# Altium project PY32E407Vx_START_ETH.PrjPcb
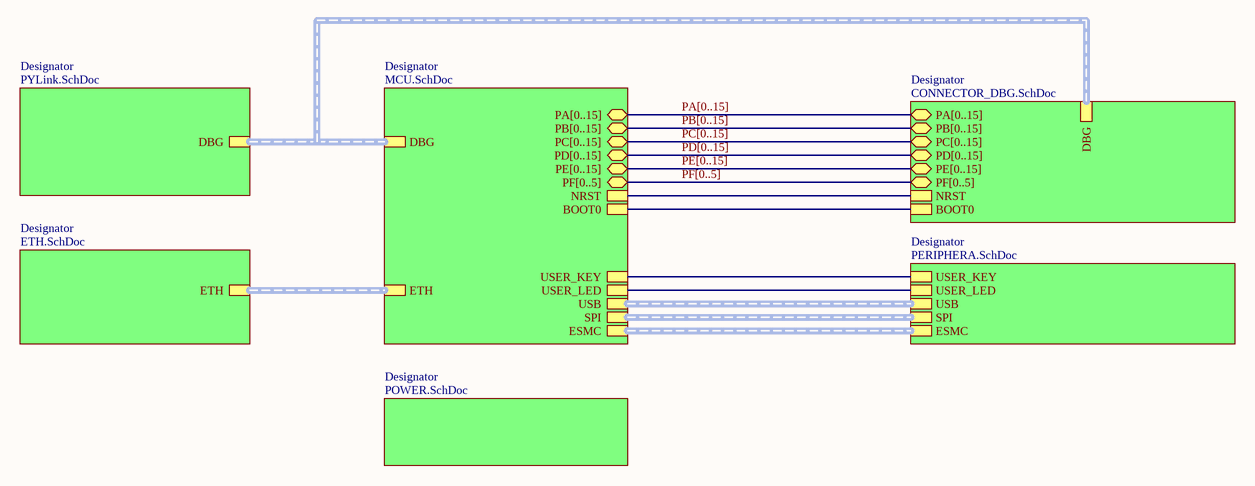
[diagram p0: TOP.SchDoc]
7 sheets, 253 parts. Net scope: hierarchical (ports join the sheet entries above them; power ports are global).
Board file: PY32E407Vx_START_ETH.PcbDoc
Sheets:
  TOP.SchDoc
    Designator = PYLink.SchDoc
    Designator = MCU.SchDoc
    Designator = ETH.SchDoc
    Designator = PERIPHERA.SchDoc
    Designator = CONNECTOR_DBG.SchDoc
    Designator = POWER.SchDoc

## Sheet TOP.SchDoc: TOP
size A4; Revision: V2.0; SheetNumber: 1; SheetTotal: 7; Project: PY32F403v1xT_START

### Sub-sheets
Designator = PYLink.SchDoc: DBG (harness QSPI)
Designator = MCU.SchDoc: PA[0..15] (bidir), PB[0..15] (bidir), PC[0..15] (bidir), PD[0..15] (bidir), PE[0..15] (bidir), NRST, BOOT0, ETH (harness QSPI), USB (harness QSPI), ESMC (harness QSPI), SPI (harness QSPI), DBG (harness QSPI), PF[0..5] (bidir), USER_KEY, USER_LED
Designator = ETH.SchDoc: ETH (harness QSPI)
Designator = PERIPHERA.SchDoc: USB (harness QSPI), ESMC (harness QSPI), SPI (harness QSPI), USER_KEY, USER_LED
Designator = CONNECTOR_DBG.SchDoc: PA[0..15] (bidir), PB[0..15] (bidir), PC[0..15] (bidir), PD[0..15] (bidir), PE[0..15] (bidir), NRST, BOOT0, DBG (harness QSPI), PF[0..5] (bidir)
Designator = POWER.SchDoc: no entries

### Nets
BOOT0: sheet Designator/BOOT0, sheet Designator/BOOT0
NRST: sheet Designator/NRST, sheet Designator/NRST
USER_KEY: sheet Designator/USER_KEY, sheet Designator/USER_KEY
USER_LED: sheet Designator/USER_LED, sheet Designator/USER_LED

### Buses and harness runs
bus PA[0..15] = sheet Designator/PA[0..15]
bus PB[0..15] = sheet Designator/PB[0..15]
bus PC[0..15] = sheet Designator/PC[0..15]
bus PD[0..15] = sheet Designator/PD[0..15]
bus PE[0..15] = sheet Designator/PE[0..15]
bus PF[0..5] = sheet Designator/PF[0..5]

## Sheet PYLink.SchDoc: PYLink
size A3; DrawnBy: lcg; Revision: V2.0; SheetNumber: 2; SheetTotal: 7; Project: PY32F403v1xT_START
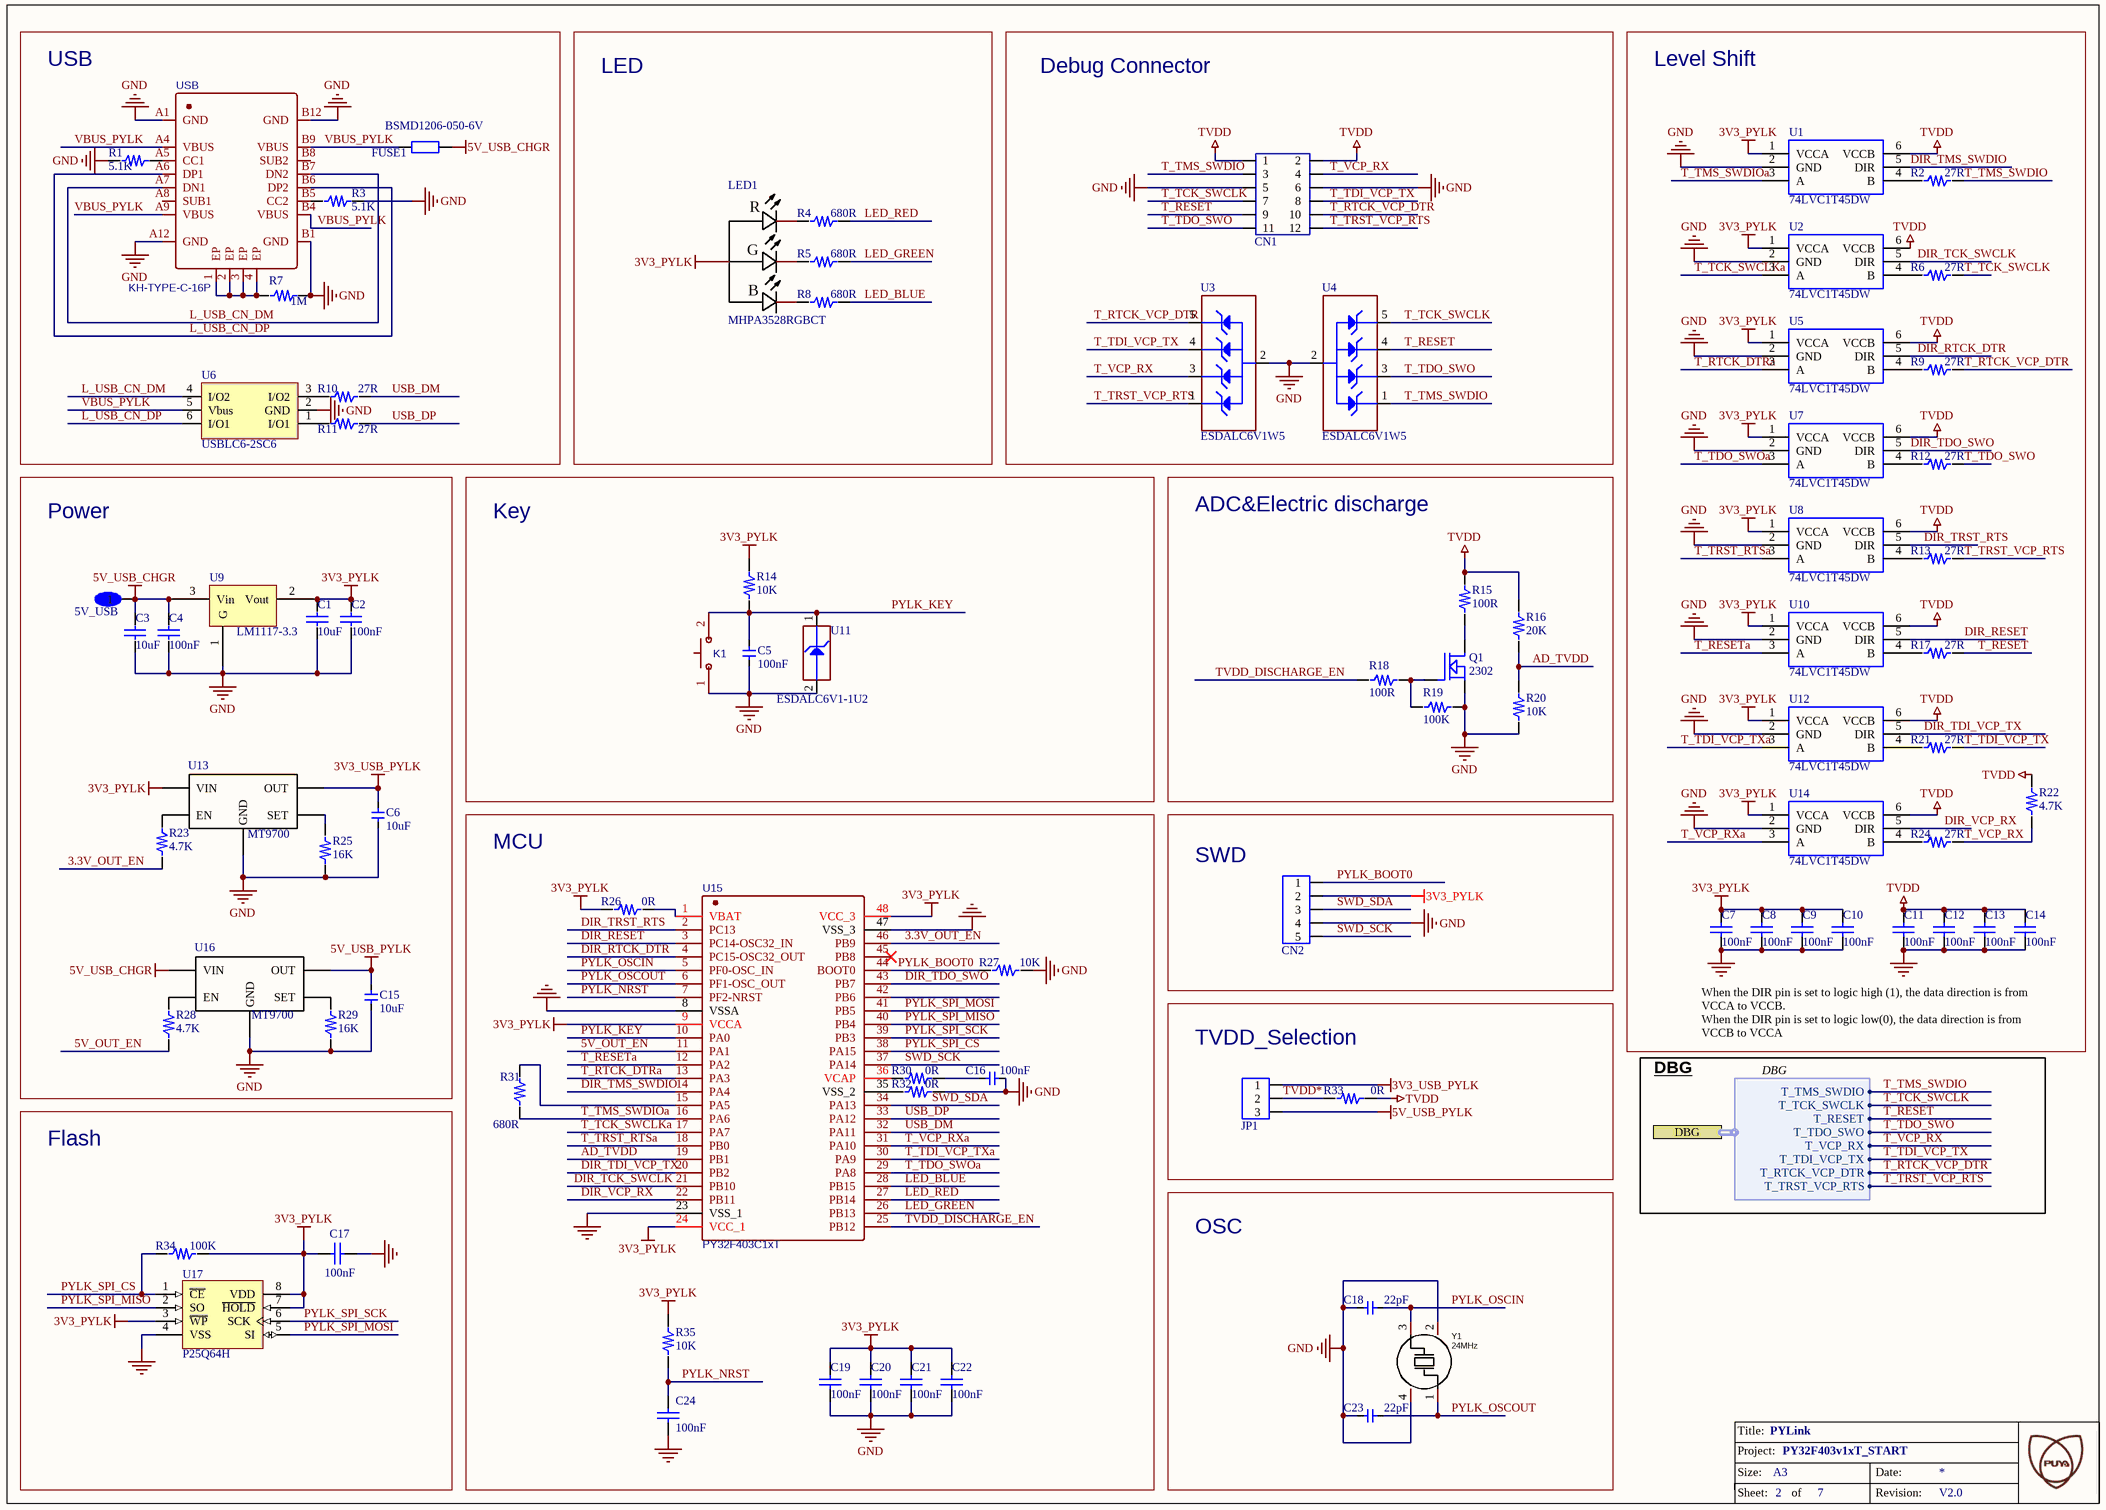
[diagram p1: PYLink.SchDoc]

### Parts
5V_USB  TP_SIN  [TP_SIN]  (value not drawn)
C1  10uF  [C0805]
C2  100nF  [C0603]
C3  10uF  [C0805]
C4  100nF  [C0603]
C5  100nF  [C0603]
C6  10uF  [C0805]
C7  100nF  [C0603]
C8  100nF  [C0603]
C9  100nF  [C0603]
C10  100nF  [C0603]
C11  100nF  [C0603]
C12  100nF  [C0603]
C13  100nF  [C0603]
C14  100nF  [C0603]
C15  10uF  [C0805]
C16  100nF  [C0603]
C17  100nF  [C0603]
C18  22pF  [C0603]
C19  100nF  [C0603]
C20  100nF  [C0603]
C21  100nF  [C0603]
C22  100nF  [C0603]
C23  22pF  [C0603]
C24  100nF  [C0603]
CN1  CON6x2  [CON6x2]  (value not drawn)
CN2  CON5  [CON5]  (value not drawn)
FUSE1  BSMD1206-050-6V  [SDM1210P005TF]
JP1  CON3  [CON3]  (value not drawn)
K1  1TS002B-2600-5001_key  [Switch]  (value not drawn)
LED1  MHPA3528RGBCT  [LED-ARRAY-SMD_4P-L3.5-W2.8-TL]
Q1  2302  [SOT23]
R1  5.1K  [R0603]
R2  27R  [R0603]
R3  5.1K  [R0603]
R4  680R  [R0603]
R5  680R  [R0603]
R6  27R  [R0603]
R7  1M  [R0603]
R8  680R  [R0603]
R9  27R  [R0603]
R10  27R  [R0603]
R11  27R  [R0603]
R12  27R  [R0603]
R13  27R  [R0603]
R14  10K  [R0603]
R15  100R  [R0805]
R16  20K  [R0603]
R17  27R  [R0603]
R18  100R  [R0603]
R19  100K  [R0603]
R20  10K  [R0603]
R21  27R  [R0603]
R22  4.7K  [R0603]
R23  4.7K  [R0603]
R24  27R  [R0603]
R25  16K  [R0603]
R26  0R  [R0603]
R27  10K  [R0603]
R28  4.7K  [R0603]
R29  16K  [R0603]
R30  0R  [R0603]
R31  680R  [R0603]
R32  0R  [R0603]
R33  0R  [R0603]
R34  100K  [R0603]
R35  10K  [R0603]
U1  74LVC1T45DW  [SOT363]
U2  74LVC1T45DW  [SOT363]
U3  value ESDALC6V1W5  [ESD_SOT323-5L]  (hidden comment: ESD_6V1)
U4  value ESDALC6V1W5  [ESD_SOT323-5L]  (hidden comment: ESD_6V1)
U5  74LVC1T45DW  [SOT363]
U6  USBLC6-2SC6  [SOT23-6]
U7  74LVC1T45DW  [SOT363]
U8  74LVC1T45DW  [SOT363]
U9  LM1117-3.3  [LM1117-3.3]
U10  74LVC1T45DW  [SOT363]
U11  value ESDALC6V1-1U2  [ESD_ST0201]  (hidden comment: ESD-TRANSIL)
U12  74LVC1T45DW  [SOT363]
U13  MT9700  [SOT23-5]
U14  74LVC1T45DW  [SOT363]
U15  PY32F403C1xT  [LQFP-48_L7.0-W7.0-P0.50-LS9.0-BL]
U16  MT9700  [SOT23-5]
U17  P25Q64H  [SOP-8P]
USB  KH-TYPE-C-16P  [USB-C-SMD_KH-TYPE-C-16P]
Y1  24MHz  [CRYSTAL-SMD_4P-L3.2-W2.5-BL]

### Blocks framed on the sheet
USB: FUSE1 R1 R3 R7 R10 R11 U6 USB
LED: LED1 R4 R5 R8
Debug Connector: CN1 U3 U4
Level Shift: C7-C14 R2 R6 R9 R12 R13 R17 R21 R22 R24 U1 U2 U5 U7 U8 U10 U12 U14
Power: 5V_USB C1-C4 C6 C15 R23 R25 R28 R29 U9 U13 U16
Key: C5 K1 R14 U11
ADC&Electric discharge: Q1 R15 R16 R18-R20
MCU: C16 C19-C22 C24 R26 R27 R30-R32 R35 U15
SWD: CN2
TVDD_Selection: JP1 R33
Flash: C17 R34 U17
OSC: C18 C23 Y1

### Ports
DBG (harness DBG)

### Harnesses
DBG: T_VCP_RX, T_TDO_SWO, T_RESET, T_TMS_SWDIO, T_TDI_VCP_TX, T_TCK_SWCLK, T_RTCK_VCP_DTR, T_TRST_VCP_RTS

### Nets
3V3_PYLK: C1.2 C2.2 C7.2 C8.2 C9.2 C10.2 C17.2 C19.2 C20.2 C21.2 C22.2 CN2.2 LED1.1(-) R14.2 R26.1 R34.2 R35.2 U1.1(VCCA) U2.1(VCCA) U5.1(VCCA) U7.1(VCCA) U8.1(VCCA) U9.2(Vout) U10.1(VCCA) U12.1(VCCA) U13.5(VIN) U14.1(VCCA) U15.9(VCCA) U15.24(VCC_1) U15.48(VCC_3) U17.3(~{WP}) U17.7(~{HOLD}) U17.8(VDD)
3V3_USB_PYLK: C6.2 JP1.1 U13.1(OUT)
5V_USB_CHGR: 5V_USB.1 C3.2 C4.2 FUSE1.2 U9.3(Vin) U16.5(VIN)
5V_USB_PYLK: C15.2 JP1.3 U16.1(OUT)
GND: C1.1 C2.1 C3.1 C4.1 C5.1 C6.1 C7.1 C8.1 C9.1 C10.1 C11.1 C12.1 C13.1 C14.1 C15.1 C16.1 C17.1 C18.1 C19.1 C20.1 C21.1 C22.1 C23.1 C24.1 CN1.5 CN1.6 CN2.4 K1.1(A) Q1.2(S) R1.1 R3.2 R7.2 R19.1 R20.1 R25.1 R27.2 R29.1 R32.2 U1.2(GND) U2.2(GND) U3.2(GND) U4.2(GND) U5.2(GND) U6.2(GND) U7.2(GND) U8.2(GND) U9.1(G) U10.2(GND) U11.2(GND) U12.2(GND) U13.2(GND) U14.2(GND) U15.8(VSSA) U15.23(VSS_1) U15.47(VSS_3) U16.2(GND) U17.4(VSS) USB.A1(GND) USB.A12(GND) USB.B1(GND) USB.B12(GND) Y1.2(GND) Y1.4(GND)
TVDD: C11.2 C12.2 C13.2 C14.2 CN1.1 CN1.2 R15.2 R16.2 R22.2 R33.2 U1.6(VCCB) U2.6(VCCB) U5.6(VCCB) U7.6(VCCB) U8.6(VCCB) U10.6(VCCB) U12.6(VCCB) U14.6(VCCB)
3.3V_OUT_EN: R23.1 U15.46(PB9)
5V_OUT_EN: R28.1 U15.11(PA1)
AD_TVDD: R16.1 R20.2 U15.19(PB1)
DIR_RESET: U10.5(DIR) U15.3(PC14-OSC32_IN)
DIR_RTCK_DTR: U5.5(DIR) U15.4(PC15-OSC32_OUT)
DIR_TCK_SWCLK: U2.5(DIR) U15.21(PB10)
DIR_TDI_VCP_TX: U12.5(DIR) U15.20(PB2)
DIR_TDO_SWO: U7.5(DIR) U15.43(PB7)
DIR_TMS_SWDIO: U1.5(DIR) U15.14(PA4)
DIR_TRST_RTS: U8.5(DIR) U15.2(PC13)
DIR_VCP_RX: U14.5(DIR) U15.22(PB11)
L_USB_CN_DM: U6.4(I/O2) USB.A7(DN1) USB.B7(DN2)
L_USB_CN_DP: U6.6(I/O1) USB.A6(DP1) USB.B6(DP2)
LED_BLUE: R8.2 U15.28(PB15)
LED_GREEN: R5.2 U15.26(PB13)
LED_RED: R4.2 U15.27(PB14)
PYLK_BOOT0: CN2.1 R27.1 U15.44(BOOT0)
PYLK_KEY: C5.2 K1.2(B) R14.1 U11.1(IO1) U15.10(PA0)
PYLK_NRST: C24.2 R35.1 U15.7(PF2-NRST)
PYLK_OSCIN: C18.2 U15.5(PF0-OSC_IN) Y1.3(OSC2)
PYLK_OSCOUT: C23.2 U15.6(PF1-OSC_OUT) Y1.1(OSC1)
PYLK_SPI_CS: R34.1 U15.38(PA15) U17.1(~{CE})
PYLK_SPI_MISO: U15.40(PB4) U17.2(SO)
PYLK_SPI_MOSI: U15.41(PB5) U17.5(SI)
PYLK_SPI_SCK: U15.39(PB3) U17.6(SCK)
SWD_SCK: CN2.5 U15.37(PA14)
SWD_SDA: CN2.3 U15.34(PA13)
T_RESET: CN1.9 R17.2 U4.4(IO3) ; port DBG.T_RESET
T_RESETa: U10.3(A) U15.12(PA2)
T_RTCK_DTRa: U5.3(A) U15.13(PA3)
T_RTCK_VCP_DTR: CN1.10 R9.2 U3.5(IO4) ; port DBG.T_RTCK_VCP_DTR
T_TCK_SWCLK: CN1.7 R6.2 U4.5(IO4) ; port DBG.T_TCK_SWCLK
T_TCK_SWCLKa: U2.3(A) U15.17(PA7)
T_TDI_VCP_TX: CN1.8 R21.2 U3.4(IO3) ; port DBG.T_TDI_VCP_TX
T_TDI_VCP_TXa: U12.3(A) U15.30(PA9)
T_TDO_SWO: CN1.11 R12.2 U4.3(IO2) ; port DBG.T_TDO_SWO
T_TDO_SWOa: U7.3(A) U15.29(PA8)
T_TMS_SWDIO: CN1.3 R2.2 U4.1(IO1) ; port DBG.T_TMS_SWDIO
T_TMS_SWDIOa: R31.1 U1.3(A) U15.16(PA6)
T_TRST_RTSa: U8.3(A) U15.18(PB0)
T_TRST_VCP_RTS: CN1.12 R13.2 U3.1(IO1) ; port DBG.T_TRST_VCP_RTS
T_VCP_RX: CN1.4 R22.1 R24.2 U3.3(IO2) ; port DBG.T_VCP_RX
T_VCP_RXa: U14.3(A) U15.31(PA10)
TVDD*: JP1.2 R33.1
TVDD_DISCHARGE_EN: R18.2 U15.25(PB12)
USB_DM: R10.2 U15.32(PA11)
USB_DP: R11.2 U15.33(PA12)
VBUS_PYLK: FUSE1.1 U6.5(Vbus) USB.A4(VBUS) USB.A9(VBUS) USB.B4(VBUS) USB.B9(VBUS)
NetC16_2: C16.2 R30.2
NetLED1_2: LED1.2(-) R8.1
NetLED1_3: LED1.3(-) R5.1
NetLED1_4: LED1.4(-) R4.1
NetQ1_1: Q1.1(G) R18.1 R19.2
NetQ1_3: Q1.3(D) R15.1
NetR1_2: R1.2 USB.A5(CC1)
NetR2_1: R2.1 U1.4(B)
NetR3_1: R3.1 USB.B5(CC2)
NetR6_1: R6.1 U2.4(B)
NetR7_1: R7.1 USB.1(EP) USB.2(EP) USB.3(EP) USB.4(EP)
NetR9_1: R9.1 U5.4(B)
NetR10_1: R10.1 U6.3(I/O2)
NetR11_1: R11.1 U6.1(I/O1)
NetR12_1: R12.1 U7.4(B)
NetR13_1: R13.1 U8.4(B)
NetR17_1: R17.1 U10.4(B)
NetR21_1: R21.1 U12.4(B)
NetR23_2: R23.2 U13.4(EN)
NetR24_1: R24.1 U14.4(B)
NetR25_2: R25.2 U13.3(SET)
NetR26_2: R26.2 U15.1(VBAT)
NetR28_2: R28.2 U16.4(EN)
NetR29_2: R29.2 U16.3(SET)
NetR30_1: R30.1 U15.36(VCAP)
NetR31_2: R31.2 U15.15(PA5)
NetR32_1: R32.1 U15.35(VSS_2)

Not connected (* = marked no-connect by the designer): U15 42(PB6) 45(PB8)*; USB A8(SUB1) B8(SUB2)

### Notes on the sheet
- When the DIR pin is set to logic high (1), the data direction is from VCCA to VCCB.
  When the DIR pin is set to logic low(0), the data direction is from VCCB to VCCA
- DBG

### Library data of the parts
C1 C3 C6 C15 = C0805: PCB DECAL: 0805
C2 C4 C5 C16 C18 C23 = C0603: PCB DECAL: 0603
C7-C14 C17 C19-C22 C24 = 贴片高压陶瓷电容: Capacitor (Semiconductor SIM Model); 器件封装(外观): 0603; Value: 104
CN1 = CON6x2: PCB DECAL: CON5x2
FUSE1 = SMD1210P005TF: https://item.szlcsc.com/947797.html?fromZone=s_s__%25226V%2520500mA%2522
K1 = 1TS002B-2600-5001_key: BOM_Manufacturer: HYP; Contributor: LCSC
LED1 = MHPA3528RGBCT: Manufacturer: MEIHUA(美华); Add into BOM: yes
Q1 = MOSFET N: Value: SI2302
R1-R14 R16-R35 = R0603: PCB DECAL: 0603
R15 = R0805: PCB DECAL: 0805
U3 U4 = ESDALC6V1W5: Dual Transil array for ESD protection; Internal_Part_Number: MCD-00136; Part_Type: Diode; Manufacturer: STMICROELECTRONICS; ECCN_US: EAR99; ECCN_EU: NEC; Provided_By: Subcon; Initial_Board_Reference: MB1262
U6 = USBLC6-2SC6: Function: ESD EMI fliter
U11 = ESD-TRANSIL: ESD protection 6V1; Internal_Part_Number: MCD-00170; Part_Type: Diode; Manufacturer: STMICROELECTRONICS; ECCN_US: EAR99; ECCN_EU: NEC; Provided_By: Subcon; Initial_Board_Reference: MB1274
U15 = PY32F403C1xT: LQFP48; BOM_Manufacturer: PUYA(普冉)
U17 = SST25VF010: Value: SST25VF020B; 器件封装(外观): SOP8
USB = KH-TYPE-C-16P: BOM_Manufacturer: Shenzhen Kinghelm Elec; Contributor: LCSC
Y1 = ABM8AIG-24.000MHZ-82Z-T: ±20ppm , 12.5pF , T_use: -40°C~125°C; Manufacturer: ABRACON; Add into BOM: yes; External load capacitor: 8pF; Frequency Stability(Full temperature range): ±50ppm; Equivalent Series Resistance (ESR): 50Ω

## Sheet MCU.SchDoc: MCU
size A3; Revision: V2.0; SheetNumber: 3; SheetTotal: 7; Project: PY32F403v1xT_START
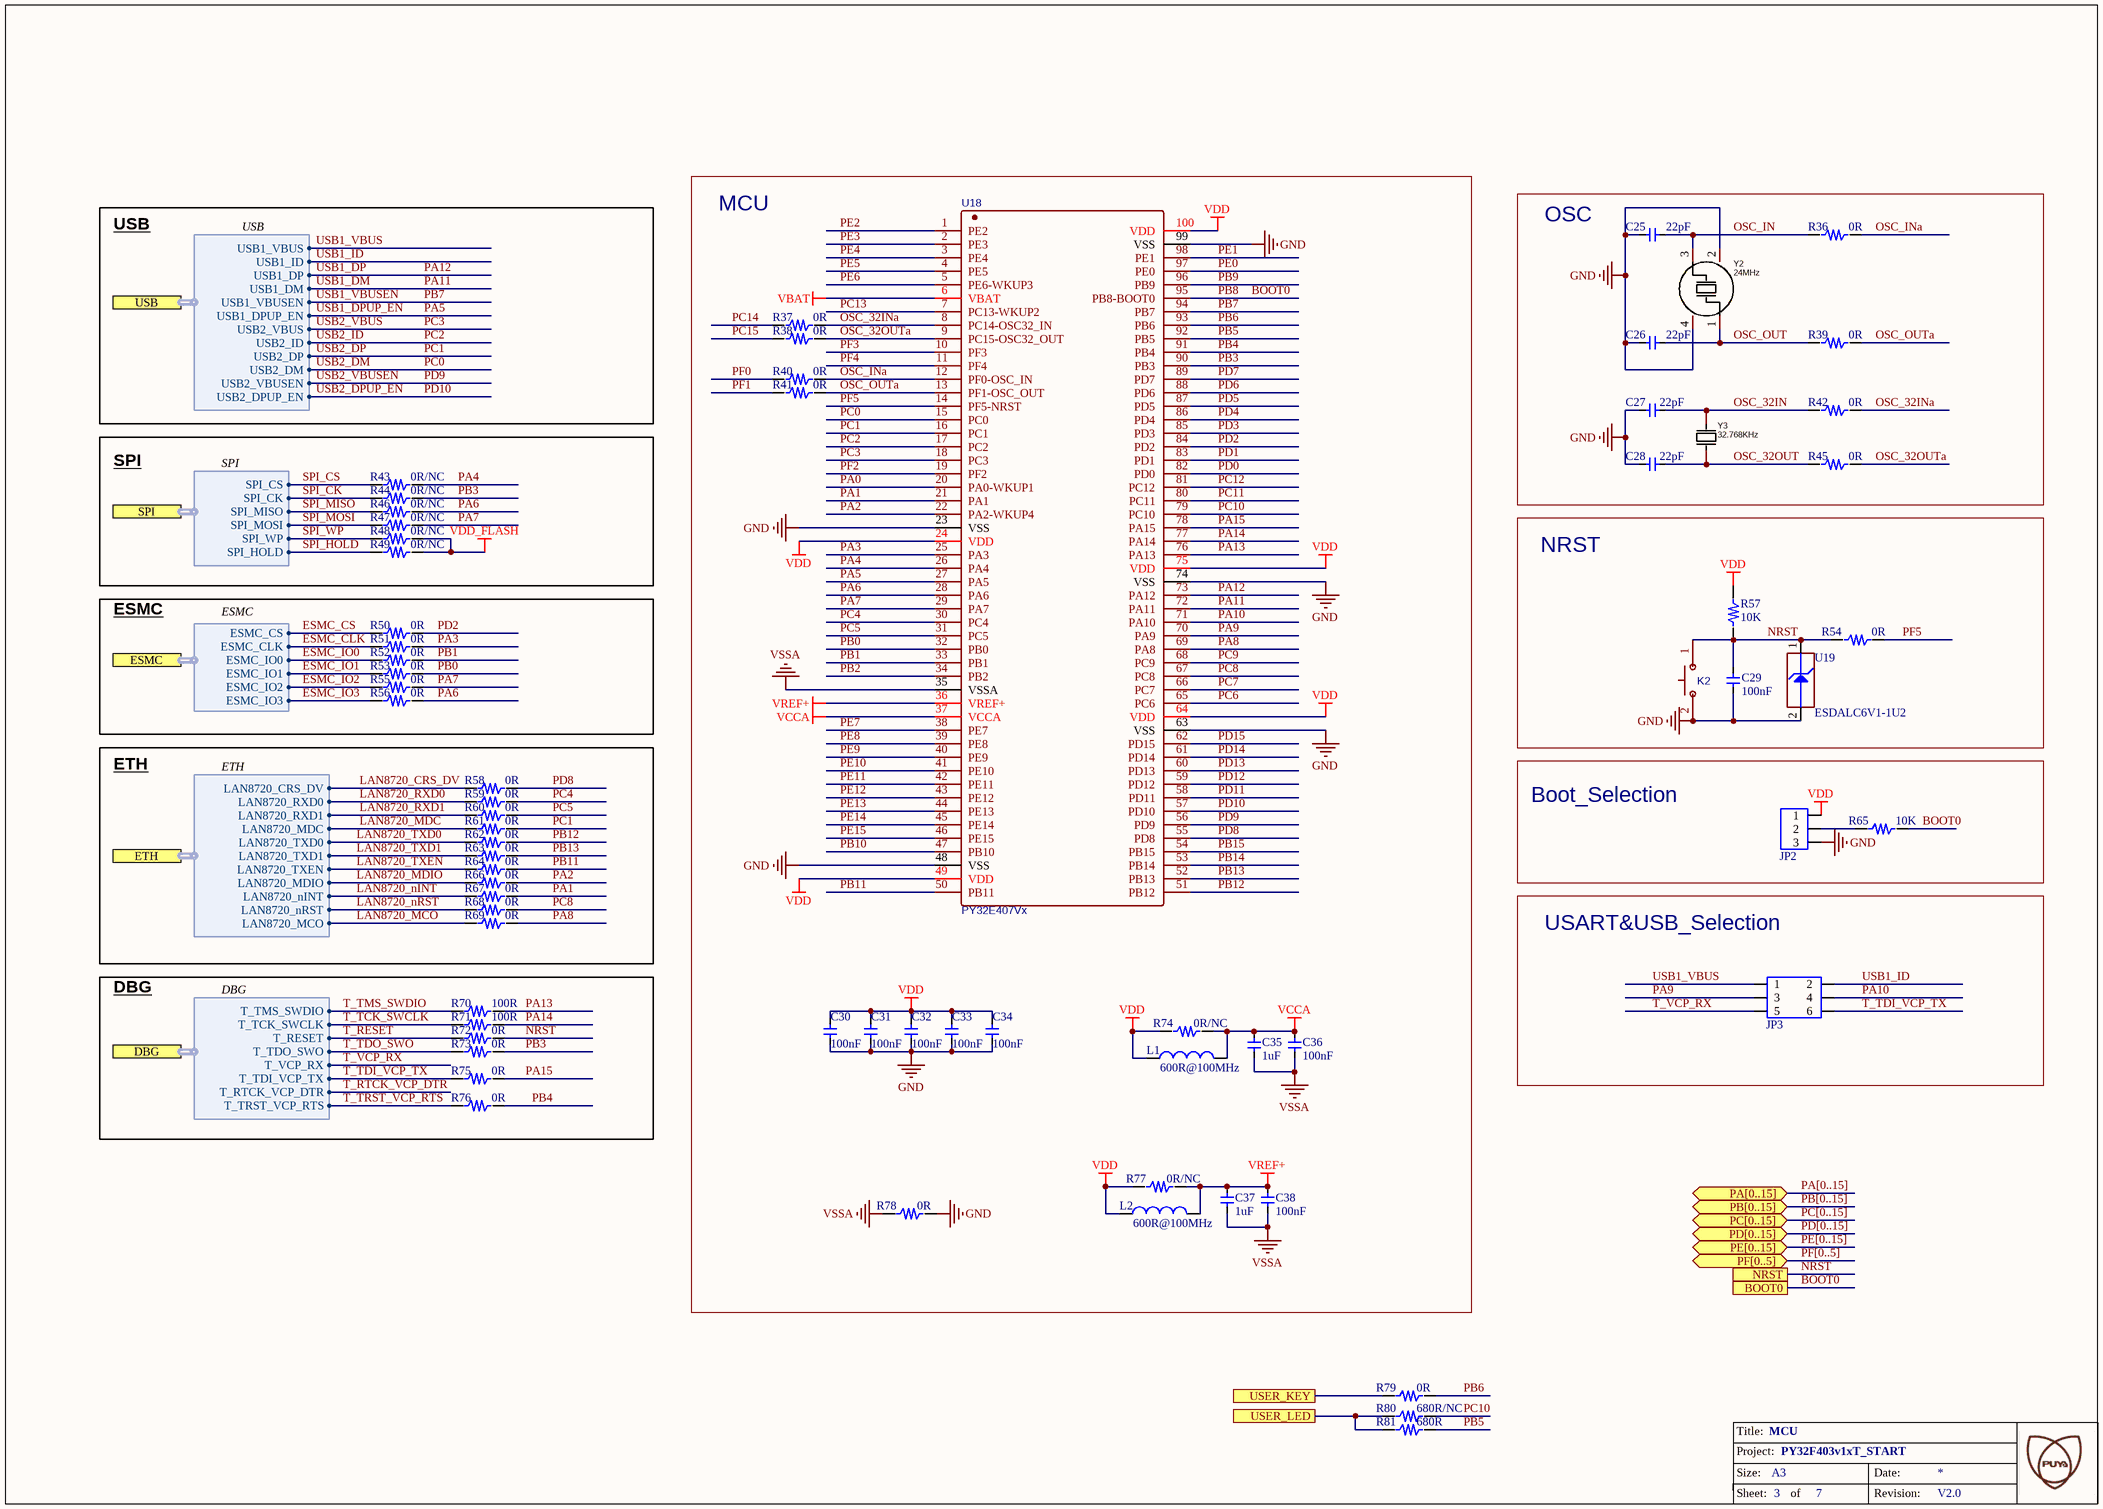
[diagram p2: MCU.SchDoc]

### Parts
C25  22pF  [C0603]
C26  22pF  [C0603]
C27  22pF  [C0603]
C28  22pF  [C0603]
C29  100nF  [C0603]
C30  100nF  [C0603]
C31  100nF  [C0603]
C32  100nF  [C0603]
C33  100nF  [C0603]
C34  100nF  [C0603]
C35  1uF  [C0805]
C36  100nF  [C0603]
C37  1uF  [C0805]
C38  100nF  [C0603]
JP2  CON3  [CON3]  (value not drawn)
JP3  CON3x2  [CON3x2]  (value not drawn)
K2  1TS002B-2600-5001_key  [Switch]  (value not drawn)
L1  value 600R@100MHz  [L0603]  (hidden comment: BEAD)
L2  value 600R@100MHz  [L0603]  (hidden comment: BEAD)
R36  0R  [R0603]
R37  0R  [R0603]
R38  0R  [R0603]
R39  0R  [R0603]
R40  0R  [R0603]
R41  0R  [R0603]
R42  0R  [R0603]
R43  0R/NC  [R0603]
R44  0R/NC  [R0603]
R45  0R  [R0603]
R46  0R/NC  [R0603]
R47  0R/NC  [R0603]
R48  0R/NC  [R0603]
R49  0R/NC  [R0603]
R50  0R  [R0603]
R51  0R  [R0603]
R52  0R  [R0603]
R53  0R  [R0603]
R54  0R  [R0603]
R55  0R  [R0603]
R56  0R  [R0603]
R57  10K  [R0603]
R58  0R  [R0603]
R59  0R  [R0603]
R60  0R  [R0603]
R61  0R  [R0603]
R62  0R  [R0603]
R63  0R  [R0603]
R64  0R  [R0603]
R65  10K  [R0603]
R66  0R  [R0603]
R67  0R  [R0603]
R68  0R  [R0603]
R69  0R  [R0603]
R70  100R  [R0603]
R71  100R  [R0603]
R72  0R  [R0603]
R73  0R  [R0603]
R74  0R/NC  [R0603]
R75  0R  [R0603]
R76  0R  [R0603]
R77  0R/NC  [R0603]
R78  0R  [R0603]
R79  0R  [R0603]
R80  680R/NC  [R0603]
R81  680R  [R0603]
U18  PY32E407Vx  [LQFP-100_L14.0-W14.0-P0.50-LS16.0-BL]
U19  value ESDALC6V1-1U2  [ESD_ST0201]  (hidden comment: ESD-TRANSIL)
Y2  24MHz  [CRYSTAL-SMD_4P-L3.2-W2.5-BL]
Y3  32.768KHz  [CRYSTAL-SMD_L3.2-W1.5-1]

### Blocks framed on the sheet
MCU: C30-C38 L1 L2 R37 R38 R40 R41 R74 R77 R78 U18
OSC: C25-C28 R36 R39 R42 R45 Y2 Y3
SPI: R43 R44 R46-R49
NRST: C29 K2 R54 R57 U19
ESMC: R50-R53 R55 R56
ETH: R58-R64 R66-R69
Boot_Selection: JP2 R65
USART&USB_Selection: JP3
DBG: R70-R73 R75 R76

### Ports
BOOT0, DBG (harness DBG), ESMC (harness ESMC), ETH (harness ETH), NRST, PA[0..15] (bidir), PB[0..15] (bidir), PC[0..15] (bidir), PD[0..15] (bidir), PE[0..15] (bidir), PF[0..5] (bidir), SPI (harness SPI), USB (harness USB), USER_KEY, USER_LED

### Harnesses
ETH: LAN8720_TXD0, LAN8720_MDC, LAN8720_RXD1, LAN8720_CRS_DV, LAN8720_TXD1, LAN8720_TXEN, LAN8720_nINT, LAN8720_MDIO, LAN8720_nRST, LAN8720_RXD0, LAN8720_MCO
ESMC: ESMC_IO2, ESMC_IO1, ESMC_IO0, ESMC_CS, ESMC_IO3, ESMC_CLK
DBG: T_VCP_RX, T_TDO_SWO, T_RESET, T_TMS_SWDIO, T_TDI_VCP_TX, T_TCK_SWCLK, T_RTCK_VCP_DTR, T_TRST_VCP_RTS
USB: USB2_VBUS, USB1_DM, USB1_DP, USB1_VBUS, USB2_ID, USB2_DP, USB2_DM, USB1_ID, USB2_VBUSEN, USB1_VBUSEN, USB1_DPUP_EN, USB2_DPUP_EN
SPI: SPI_MOSI, SPI_MISO, SPI_CS, SPI_CK, SPI_WP, SPI_HOLD

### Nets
GND: C25.1 C26.1 C27.1 C28.1 C29.1 C30.1 C31.1 C32.1 C33.1 C34.1 JP2.3 K2.2(B) R78.2 U18.23(VSS) U18.48(VSS) U18.63(VSS) U18.74(VSS) U18.99(VSS) U19.2(GND) Y2.2(GND) Y2.4(GND)
VBAT: U18.6(VBAT)
VCCA: C35.2 C36.2 L1.2 R74.2 U18.37(VCCA)
VDD: C30.2 C31.2 C32.2 C33.2 C34.2 JP2.1 L1.1 L2.1 R57.1 R74.1 R77.1 U18.24(VDD) U18.49(VDD) U18.64(VDD) U18.75(VDD) U18.100(VDD)
VDD_FLASH: R48.2 R49.2
VREF+: C37.2 C38.2 L2.2 R77.2 U18.36(VREF+)
VSSA: C35.1 C36.1 C37.1 C38.1 R78.1 U18.35(VSSA)
BOOT0: R65.2 U18.95(PB8-BOOT0) ; port BOOT0  [also labelled PB8]
ESMC_CLK: R44.1 R51.1 ; port ESMC.ESMC_CLK, port SPI.SPI_CK  [also labelled SPI_CK]
ESMC_CS: R43.1 R50.1 ; port ESMC.ESMC_CS, port SPI.SPI_CS  [also labelled SPI_CS]
ESMC_IO0: R47.1 R52.1 ; port ESMC.ESMC_IO0, port SPI.SPI_MOSI  [also labelled SPI_MOSI]
ESMC_IO1: R46.1 R53.1 ; port ESMC.ESMC_IO1, port SPI.SPI_MISO  [also labelled SPI_MISO]
ESMC_IO2: R48.1 R55.1 ; port ESMC.ESMC_IO2, port SPI.SPI_WP  [also labelled SPI_WP]
ESMC_IO3: R49.1 R56.1 ; port ESMC.ESMC_IO3, port SPI.SPI_HOLD  [also labelled SPI_HOLD]
LAN8720_CRS_DV: R58.1 ; port ETH.LAN8720_CRS_DV
LAN8720_MCO: R69.1 ; port ETH.LAN8720_MCO
LAN8720_MDC: R61.1 ; port ETH.LAN8720_MDC
LAN8720_MDIO: R66.1 ; port ETH.LAN8720_MDIO
LAN8720_nINT: R67.1 ; port ETH.LAN8720_nINT
LAN8720_nRST: R68.1 ; port ETH.LAN8720_nRST
LAN8720_RXD0: R59.1 ; port ETH.LAN8720_RXD0
LAN8720_RXD1: R60.1 ; port ETH.LAN8720_RXD1
LAN8720_TXD0: R62.1 ; port ETH.LAN8720_TXD0
LAN8720_TXD1: R63.1 ; port ETH.LAN8720_TXD1
LAN8720_TXEN: R64.1 ; port ETH.LAN8720_TXEN
NRST: C29.2 K2.1(A) R54.1 R57.2 R72.2 U19.1(IO1) ; port NRST
OSC_32IN: C27.2 R42.1 Y3.2(OSC2)
OSC_32INa: R37.2 R42.2 U18.8(PC14-OSC32_IN)
OSC_32OUT: C28.2 R45.1 Y3.1(OSC1)
OSC_32OUTa: R38.2 R45.2 U18.9(PC15-OSC32_OUT)
OSC_IN: C25.2 R36.1 Y2.3(OSC2)
OSC_INa: R36.2 R40.2 U18.12(PF0-OSC_IN)
OSC_OUT: C26.2 R39.1 Y2.1(OSC1)
OSC_OUTa: R39.2 R41.2 U18.13(PF1-OSC_OUT)
PA0: U18.20(PA0-WKUP1)
PA1: R67.2 U18.21(PA1)
PA2: R66.2 U18.22(PA2-WKUP4)
PA3: R51.2 U18.25(PA3)
PA4: R43.2 U18.26(PA4)
PA5: U18.27(PA5) ; port USB.USB1_DPUP_EN  [also labelled USB1_DPUP_EN]
PA6: R46.2 R56.2 U18.28(PA6)
PA7: R47.2 R55.2 U18.29(PA7)
PA8: R69.2 U18.69(PA8)
PA9: JP3.3 U18.70(PA9)
PA10: JP3.4 U18.71(PA10)
PA11: U18.72(PA11) ; port USB.USB1_DM  [also labelled USB1_DM]
PA12: U18.73(PA12) ; port USB.USB1_DP  [also labelled USB1_DP]
PA13: R70.2 U18.76(PA13)
PA14: R71.2 U18.77(PA14)
PA15: R75.2 U18.78(PA15)
PB0: R53.2 U18.32(PB0)
PB1: R52.2 U18.33(PB1)
PB2: U18.34(PB2)
PB3: R44.2 R73.2 U18.90(PB3)
PB4: R76.2 U18.91(PB4)
PB5: R81.2 U18.92(PB5)
PB6: R79.2 U18.93(PB6)
PB7: U18.94(PB7) ; port USB.USB1_VBUSEN  [also labelled USB1_VBUSEN]
PB9: U18.96(PB9)
PB10: U18.47(PB10)
PB11: R64.2 U18.50(PB11)
PB12: R62.2 U18.51(PB12)
PB13: R63.2 U18.52(PB13)
PB14: U18.53(PB14)
PB15: U18.54(PB15)
PC0: U18.15(PC0) ; port USB.USB2_DM  [also labelled USB2_DM]
PC1: R61.2 U18.16(PC1) ; port USB.USB2_DP  [also labelled USB2_DP]
PC2: U18.17(PC2) ; port USB.USB2_ID  [also labelled USB2_ID]
PC3: U18.18(PC3) ; port USB.USB2_VBUS  [also labelled USB2_VBUS]
PC4: R59.2 U18.30(PC4)
PC5: R60.2 U18.31(PC5)
PC6: U18.65(PC6)
PC7: U18.66(PC7)
PC8: R68.2 U18.67(PC8)
PC9: U18.68(PC9)
PC10: R80.2 U18.79(PC10)
PC11: U18.80(PC11)
PC12: U18.81(PC12)
PC13: U18.7(PC13-WKUP2)
PC14: R37.1
PC15: R38.1
PD0: U18.82(PD0)
PD1: U18.83(PD1)
PD2: R50.2 U18.84(PD2)
PD3: U18.85(PD3)
PD4: U18.86(PD4)
PD5: U18.87(PD5)
PD6: U18.88(PD6)
PD7: U18.89(PD7)
PD8: R58.2 U18.55(PD8)
PD9: U18.56(PD9) ; port USB.USB2_VBUSEN  [also labelled USB2_VBUSEN]
PD10: U18.57(PD10) ; port USB.USB2_DPUP_EN  [also labelled USB2_DPUP_EN]
PD11: U18.58(PD11)
PD12: U18.59(PD12)
PD13: U18.60(PD13)
PD14: U18.61(PD14)
PD15: U18.62(PD15)
PE0: U18.97(PE0)
PE1: U18.98(PE1)
PE2: U18.1(PE2)
PE3: U18.2(PE3)
PE4: U18.3(PE4)
PE5: U18.4(PE5)
PE6: U18.5(PE6-WKUP3)
PE7: U18.38(PE7)
PE8: U18.39(PE8)
PE9: U18.40(PE9)
PE10: U18.41(PE10)
PE11: U18.42(PE11)
PE12: U18.43(PE12)
PE13: U18.44(PE13)
PE14: U18.45(PE14)
PE15: U18.46(PE15)
PF0: R40.1
PF1: R41.1
PF2: U18.19(PF2)
PF3: U18.10(PF3)
PF4: U18.11(PF4)
PF5: R54.2 U18.14(PF5-NRST)
T_RESET: R72.1 ; port DBG.T_RESET
T_TCK_SWCLK: R71.1 ; port DBG.T_TCK_SWCLK
T_TDI_VCP_TX: JP3.6 R75.1 ; port DBG.T_TDI_VCP_TX
T_TDO_SWO: R73.1 ; port DBG.T_TDO_SWO
T_TMS_SWDIO: R70.1
T_TRST_VCP_RTS: R76.1 ; port DBG.T_TRST_VCP_RTS
T_VCP_RX: JP3.5 ; port DBG.T_VCP_RX
USB1_ID: JP3.2 ; port USB.USB1_ID
USB1_VBUS: JP3.1 ; port USB.USB1_VBUS
USER_KEY: R79.1 ; port USER_KEY
USER_LED: R80.1 R81.1 ; port USER_LED
NetJP2_2: JP2.2 R65.1

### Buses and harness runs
bus PA[0..15] = port PA[0..15]
bus PB[0..15] = port PB[0..15]
bus PC[0..15] = port PC[0..15]
bus PD[0..15] = port PD[0..15]
bus PE[0..15] = port PE[0..15]
bus PF[0..5] = port PF[0..5]

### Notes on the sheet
- USB

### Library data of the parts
C25-C34 C36 C38 = C0603: PCB DECAL: 0603
C35 C37 = C0805: PCB DECAL: 0805
JP3 = CON3x2: PCB DECAL: CON5x2
K2 = 1TS002B-2600-5001_key: BOM_Manufacturer: HYP; Contributor: LCSC
L1 L2 = BEAD: SMD Chip ferrite bead, 600R@100MHz +/-25%, 350mA, 500mohm DC, 0603, T=0.8mm; Internal_Part_Number: MCD-00047; Part_Type: Inductor; Manufacturer_Part_Number: FCM1608KF-601T03; Manufacturer: TAI-TECH; Provided_By: SUBCO
R36-R81 = R0603: PCB DECAL: 0603
U18 = PY32E407Vx: LQFP100; BOM_Manufacturer: PUYA(普冉)
U19 = ESD-TRANSIL: as U11 on sheet PYLink
Y2 = ABM8AIG-24.000MHZ-82Z-T: ±20ppm , 12.5pF , T_use: -40°C~85°C  C2682775; Manufacturer: ABRACON; Add into BOM: yes; External load capacitor: 8pF; Frequency Stability(Full temperature range): ±50ppm; Equivalent Series Resistance (ESR): 50Ω
Y3 = XKXGI-SUA-32.768K: ±20ppm , 12.5pF , T_use: -40°C~125°C; Manufacturer: YXC(扬兴晶振); Add into BOM: yes; Crystal Type: 贴片晶振; Frequency Stability(Full temperature range): ±30ppm

## Sheet ETH.SchDoc: PERIPHERA
size A4; Revision: V2.0; SheetNumber: 5; SheetTotal: 7; Project: PY32F403v1xT_START
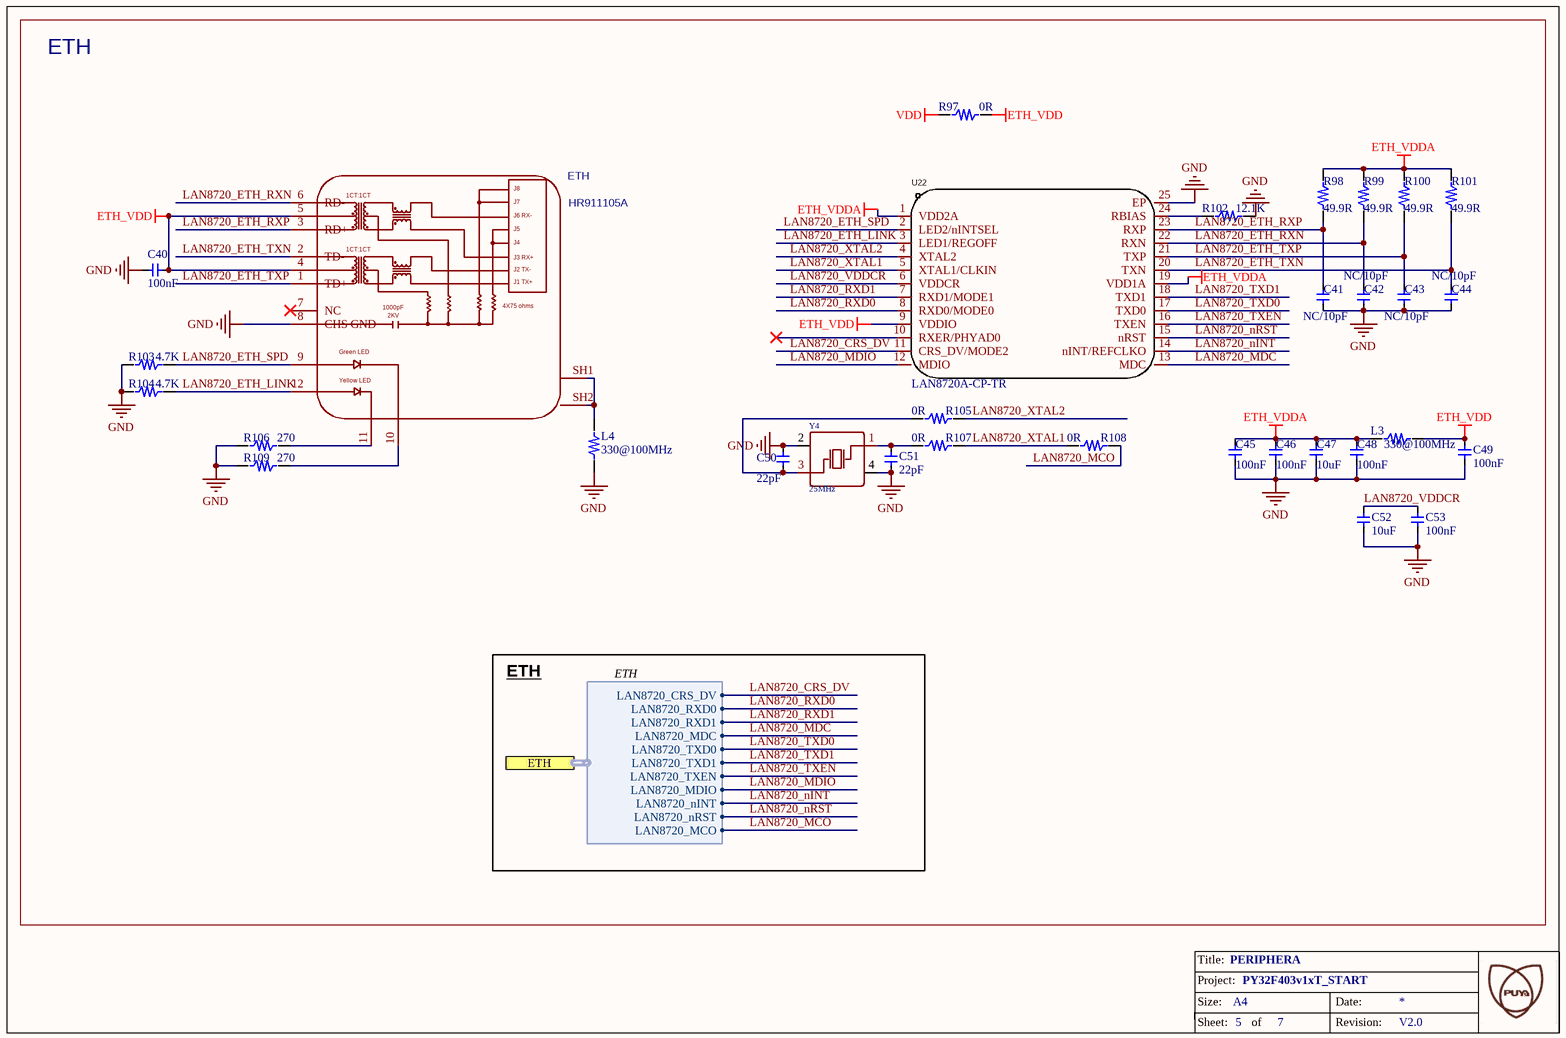
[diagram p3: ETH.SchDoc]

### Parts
C40  100nF  [C0603]
C41  NC/10pF  [C0603]
C42  NC/10pF  [C0603]
C43  NC/10pF  [C0603]
C44  NC/10pF  [C0603]
C45  100nF  [C0603]
C46  100nF  [C0603]
C47  10uF  [C0603]
C48  100nF  [C0603]
C49  100nF  [C0603]
C50  22pF  [C0603]
C51  22pF  [C0603]
C52  10uF  [C0603]
C53  100nF  [C0603]
ETH  HR911105A  [RJ45-TH_HR911105A]
L3  330@100MHz  [R0603]
L4  330@100MHz  [R0603]
R97  0R  [RES0603]
R98  49.9R  [R0603]
R99  49.9R  [R0603]
R100  49.9R  [R0603]
R101  49.9R  [R0603]
R102  12.1K  [R0603]
R103  4.7K  [R0603]
R104  4.7K  [R0603]
R105  0R  [R0603]
R106  270  [R0603]
R107  0R  [R0603]
R108  0R  [R0603]
R109  270  [R0603]
U22  LAN8720A-CP-TR  [QFN-24_L4.0-W4.0-P0.50-BL-EP2.6]
Y4  25MHz  [SMD-3225_4P]

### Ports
ETH (harness ETH)

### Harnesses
ETH: LAN8720_TXD0, LAN8720_MDC, LAN8720_RXD1, LAN8720_CRS_DV, LAN8720_TXD1, LAN8720_TXEN, LAN8720_nINT, LAN8720_MDIO, LAN8720_nRST, LAN8720_RXD0, LAN8720_MCO

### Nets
ETH_VDD: C40.2 C49.2 ETH.4 ETH.5 L3.2 R97.2 U22.9(VDDIO)
ETH_VDDA: C45.2 C46.2 C47.2 C48.2 L3.1 R98.2 R99.2 R100.2 R101.2 U22.1(VDD2A) U22.19(VDD1A)
GND: C40.1 C41.1 C42.1 C43.1 C44.1 C45.1 C46.1 C47.1 C48.1 C49.1 C50.2 C51.1 C52.1 C53.1 ETH.8(CHS_GND) L4.1 R102.2 R103.1 R104.1 R106.1 R109.1 U22.25(EP) Y4.2(GND) Y4.4(GND)
VDD: R97.1
LAN8720_CRS_DV: U22.11(CRS_DV/MODE2) ; port ETH.LAN8720_CRS_DV
LAN8720_ETH_LINK: ETH.12 R104.2 U22.3(LED1/REGOFF)
LAN8720_ETH_RXN: C42.2 ETH.6(RD-) R99.1 U22.22(RXN)
LAN8720_ETH_RXP: C41.2 ETH.3(RD+) R98.1 U22.23(RXP)
LAN8720_ETH_SPD: ETH.9 R103.2 U22.2(LED2/nINTSEL)
LAN8720_ETH_TXN: C44.2 ETH.2(TD-) R101.1 U22.20(TXN)
LAN8720_ETH_TXP: C43.2 ETH.1(TD+) R100.1 U22.21(TXP)
LAN8720_MCO: R108.2 ; port ETH.LAN8720_MCO
LAN8720_MDC: U22.13(MDC) ; port ETH.LAN8720_MDC
LAN8720_MDIO: U22.12(MDIO) ; port ETH.LAN8720_MDIO
LAN8720_nINT: U22.14(nINT/REFCLKO) ; port ETH.LAN8720_nINT
LAN8720_nRST: U22.15(nRST) ; port ETH.LAN8720_nRST
LAN8720_RXD0: U22.8(RXD0/MODE0) ; port ETH.LAN8720_RXD0
LAN8720_RXD1: U22.7(RXD1/MODE1) ; port ETH.LAN8720_RXD1
LAN8720_TXD0: U22.17(TXD0) ; port ETH.LAN8720_TXD0
LAN8720_TXD1: U22.18(TXD1) ; port ETH.LAN8720_TXD1
LAN8720_TXEN: U22.16(TXEN) ; port ETH.LAN8720_TXEN
LAN8720_VDDCR: C52.2 C53.2 U22.6(VDDCR)
LAN8720_XTAL1: R107.2 R108.1 U22.5(XTAL1/CLKIN)
LAN8720_XTAL2: R105.2 U22.4(XTAL2)
NetC50_1: C50.1 R105.1 Y4.3(OSC2)
NetC51_2: C51.2 R107.1 Y4.1(OSC1)
NetETH_10: ETH.10 R109.2
NetETH_11: ETH.11 R106.2
NetETH_SH1: ETH.SH1 ETH.SH2 L4.2
NetR102_1: R102.1 U22.24(RBIAS)

Not connected (* = marked no-connect by the designer): ETH 7(NC)*; U22 10(RXER/PHYAD0)*

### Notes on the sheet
- ETH

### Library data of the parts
C40-C53 = C0603: PCB DECAL: 0603
ETH = HR911105A_C12074: Manufacturer: HANRUN; Contributor: 13471635540
L3 L4 R98-R109 = R0603: PCB DECAL: 0603
R97 = R0805: PCB DECAL: 0805
U22 = LAN8720A-CP-TR: 立创 C45223; Manufacturer: MICROCHIP(美国微芯); Add into BOM: yes; Application Function: 以太网收发器; Number of Channels: 1; Interface: RMII; Supply Voltage: 1.6V~3.6V
Y4 = 12MHz: BOM_Manufacturer: TAE; BOM_Manufacturer Part: SMD-3225_4P12M20pf10ppm; nameAlias: Frequency; Contributor: LCSC; SMT Type: Extend

## Sheet PERIPHERA.SchDoc: PERIPHERA
size A4; Revision: V2.0; SheetNumber: 7; SheetTotal: 7; Project: PY32F403v1xT_START
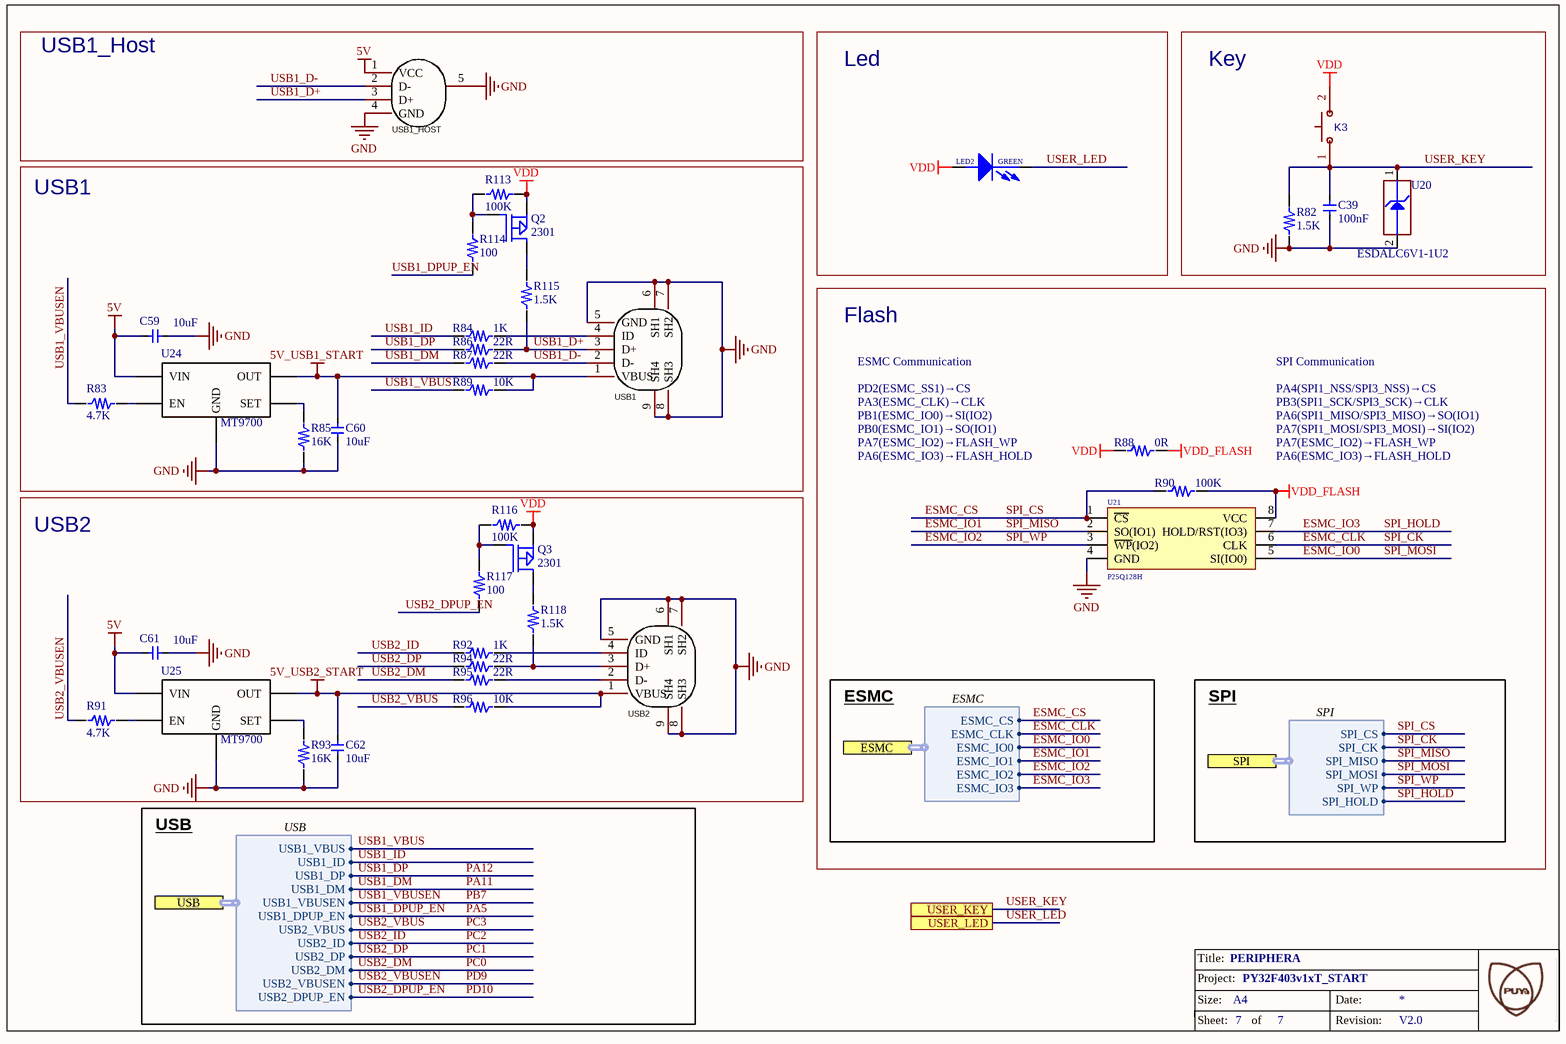
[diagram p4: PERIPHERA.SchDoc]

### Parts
C39  100nF  [C0603]
C59  10uF  [C0805]
C60  10uF  [C0805]
C61  10uF  [C0805]
C62  10uF  [C0805]
K3  1TS002B-2600-5001_key  [Switch]  (value not drawn)
LED2  GREEN  [0603_LED]
Q2  2301  [SOT23 2301]
Q3  2301  [SOT23 2301]
R82  1.5K  [R0603]
R83  4.7K  [R0603]
R84  1K  [R0603]
R85  16K  [R0603]
R86  22R  [R0603]
R87  22R  [R0603]
R88  0R  [R0603]
R89  10K  [R0603]
R90  100K  [R0603]
R91  4.7K  [R0603]
R92  1K  [R0603]
R93  16K  [R0603]
R94  22R  [R0603]
R95  22R  [R0603]
R96  10K  [R0603]
R113  100K  [R0603]
R114  100  [R0603]
R115  1.5K  [R0603]
R116  100K  [R0603]
R117  100  [R0603]
R118  1.5K  [R0603]
U20  value ESDALC6V1-1U2  [ESD_ST0201]  (hidden comment: ESD-TRANSIL)
U21  P25Q128H  [SOP8W_L]
U24  MT9700  [SOT23-5]
U25  MT9700  [SOT23-5]
USB1  Micro-B  [MICRO-USB-SMD_MICROXNJ]  (value not drawn)
USB1_HOST  Type-A  [USB-A-TH_AF-WJDG]  (value not drawn)
USB2  Micro-B  [MICRO-USB-SMD_MICROXNJ]  (value not drawn)

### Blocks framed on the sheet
USB1_Host: USB1_HOST
Led: LED2
Key: C39 K3 R82 U20
USB1: C59 C60 Q2 R83-R87 R89 R113-R115 U24 USB1
Flash: R88 R90 U21
USB2: C61 C62 Q3 R91-R96 R116-R118 U25 USB2

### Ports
ESMC (harness ESMC), SPI (harness SPI), USB (harness USB), USER_KEY, USER_LED

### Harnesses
ESMC: ESMC_IO2, ESMC_IO1, ESMC_IO0, ESMC_CS, ESMC_IO3, ESMC_CLK
SPI: SPI_MOSI, SPI_MISO, SPI_CS, SPI_CK, SPI_WP, SPI_HOLD
USB: USB2_VBUS, USB1_DM, USB1_DP, USB1_VBUS, USB2_ID, USB2_DP, USB2_DM, USB1_ID, USB2_VBUSEN, USB1_VBUSEN, USB1_DPUP_EN, USB2_DPUP_EN

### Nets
5V: C59.2 C61.2 U24.5(VIN) U25.5(VIN) USB1_HOST.1(VCC)
5V_USB1_START: C60.2 R89.2 U24.1(OUT) USB1.1(VBUS)
5V_USB2_START: C62.2 R96.2 U25.1(OUT) USB2.1(VBUS)
GND: C39.1 C59.1 C60.1 C61.1 C62.1 R82.1 R85.1 R93.1 U20.2(GND) U21.4(GND) U24.2(GND) U25.2(GND) USB1.5(GND) USB1.6(SH1) USB1.7(SH2) USB1.8(SH3) USB1.9(SH4) USB1_HOST.4(GND) USB1_HOST.5(SHLD) USB2.5(GND) USB2.6(SH1) USB2.7(SH2) USB2.8(SH3) USB2.9(SH4)
VDD: K3.2(B) LED2.1(ANODE) Q2.2(S) Q3.2(S) R88.1 R113.1 R116.1
VDD_FLASH: R88.2 R90.2 U21.8(VCC)
ESMC_CLK: U21.6(CLK) ; port ESMC.ESMC_CLK, port SPI.SPI_CK  [also labelled SPI_CK]
ESMC_CS: R90.1 U21.1(~{CS}) ; port ESMC.ESMC_CS, port SPI.SPI_CS  [also labelled SPI_CS]
ESMC_IO0: U21.5(SI(IO0)) ; port ESMC.ESMC_IO0, port SPI.SPI_MOSI  [also labelled SPI_MOSI]
ESMC_IO1: U21.2(SO(IO1)) ; port ESMC.ESMC_IO1, port SPI.SPI_MISO  [also labelled SPI_MISO]
ESMC_IO2: U21.3(~{WP}(IO2)) ; port ESMC.ESMC_IO2, port SPI.SPI_WP  [also labelled SPI_WP]
ESMC_IO3: U21.7(HOLD/RST(IO3)) ; port ESMC.ESMC_IO3, port SPI.SPI_HOLD  [also labelled SPI_HOLD]
PA5: R114.2 ; port USB.USB1_DPUP_EN  [also labelled USB1_DPUP_EN]
PA11: R87.1 ; port USB.USB1_DM  [also labelled USB1_DM]
PA12: R86.1 ; port USB.USB1_DP  [also labelled USB1_DP]
PB7: R83.1 ; port USB.USB1_VBUSEN  [also labelled USB1_VBUSEN]
PC0: R95.1 ; port USB.USB2_DM  [also labelled USB2_DM]
PC1: R94.1 ; port USB.USB2_DP  [also labelled USB2_DP]
PC2: R92.1 ; port USB.USB2_ID  [also labelled USB2_ID]
PC3: R96.1 ; port USB.USB2_VBUS  [also labelled USB2_VBUS]
PD9: R91.1 ; port USB.USB2_VBUSEN  [also labelled USB2_VBUSEN]
PD10: R117.2 ; port USB.USB2_DPUP_EN  [also labelled USB2_DPUP_EN]
USB1_D+: R86.2 R115.1 USB1.3(D+) USB1_HOST.3(D+)
USB1_D-: R87.2 USB1.2(D-) USB1_HOST.2(D-)
USB1_ID: R84.1 ; port USB.USB1_ID
USB1_VBUS: R89.1 ; port USB.USB1_VBUS
USER_KEY: C39.2 K3.1(A) R82.2 U20.1(IO1) ; port USER_KEY
USER_LED: LED2.2(CATHODE) ; port USER_LED
NetQ2_1: Q2.1(G) R113.2 R114.1
NetQ2_3: Q2.3(D) R115.2
NetQ3_1: Q3.1(G) R116.2 R117.1
NetQ3_3: Q3.3(D) R118.2
NetR83_2: R83.2 U24.4(EN)
NetR84_2: R84.2 USB1.4(ID)
NetR85_2: R85.2 U24.3(SET)
NetR91_2: R91.2 U25.4(EN)
NetR92_2: R92.2 USB2.4(ID)
NetR93_2: R93.2 U25.3(SET)
NetR94_2: R94.2 R118.1 USB2.3(D+)
NetR95_2: R95.2 USB2.2(D-)

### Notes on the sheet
- ESMC Communication
- SPI Communication
- PA3(ESMC_CLK)→CLK
- PB0(ESMC_IO1)→SO(IO1)
- PB1(ESMC_IO0)→SI(IO2)
- PD2(ESMC_SS1)→CS
- PA7(ESMC_IO2)→FLASH_WP
- PB3(SPI1_SCK/SPI3_SCK)→CLK
- PA6(SPI1_MISO/SPI3_MISO)→SO(IO1)
- PA7(SPI1_MOSI/SPI3_MOSI)→SI(IO2)
- PA4(SPI1_NSS/SPI3_NSS)→CS
- PA6(ESMC_IO3)→FLASH_HOLD
- ESMC
- SPI
- USB

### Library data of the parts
C39 = C0603: PCB DECAL: 0603
C59-C62 = C0805: PCB DECAL: 0805
K3 = 1TS002B-2600-5001_key: BOM_Manufacturer: HYP; Contributor: LCSC
LED2 = PDI-E803_Dup1
Q2 Q3 = MOSFET P: Value: SI2301; 器件封装(外观): SOT23
R82-R96 R113-R118 = R0603: PCB DECAL: 0603
U20 = ESD-TRANSIL: as U11 on sheet PYLink
U21 = W25Q256: 外置flash
USB1 USB2 = MicroXNJ: Manufacturer: SHOU HAN(首韩); Add into BOM: yes; Gender: 母; Number of Ports: 1; Number of Contacts: 5P; Current Rating - Power (Max): 1A
USB1_HOST = AF 90° WJDG: Manufacturer: SHOU HAN(首韩); Add into BOM: yes; Gender: 母; Number of Ports: 1; Number of Contacts: 4P; Current Rating - Power (Max): 1.5A

## Sheet CONNECTOR_DBG.SchDoc: CONNECTOR
size A4; Revision: V2.0; SheetNumber: 6; SheetTotal: 7; Project: PY32F403v1xT_START
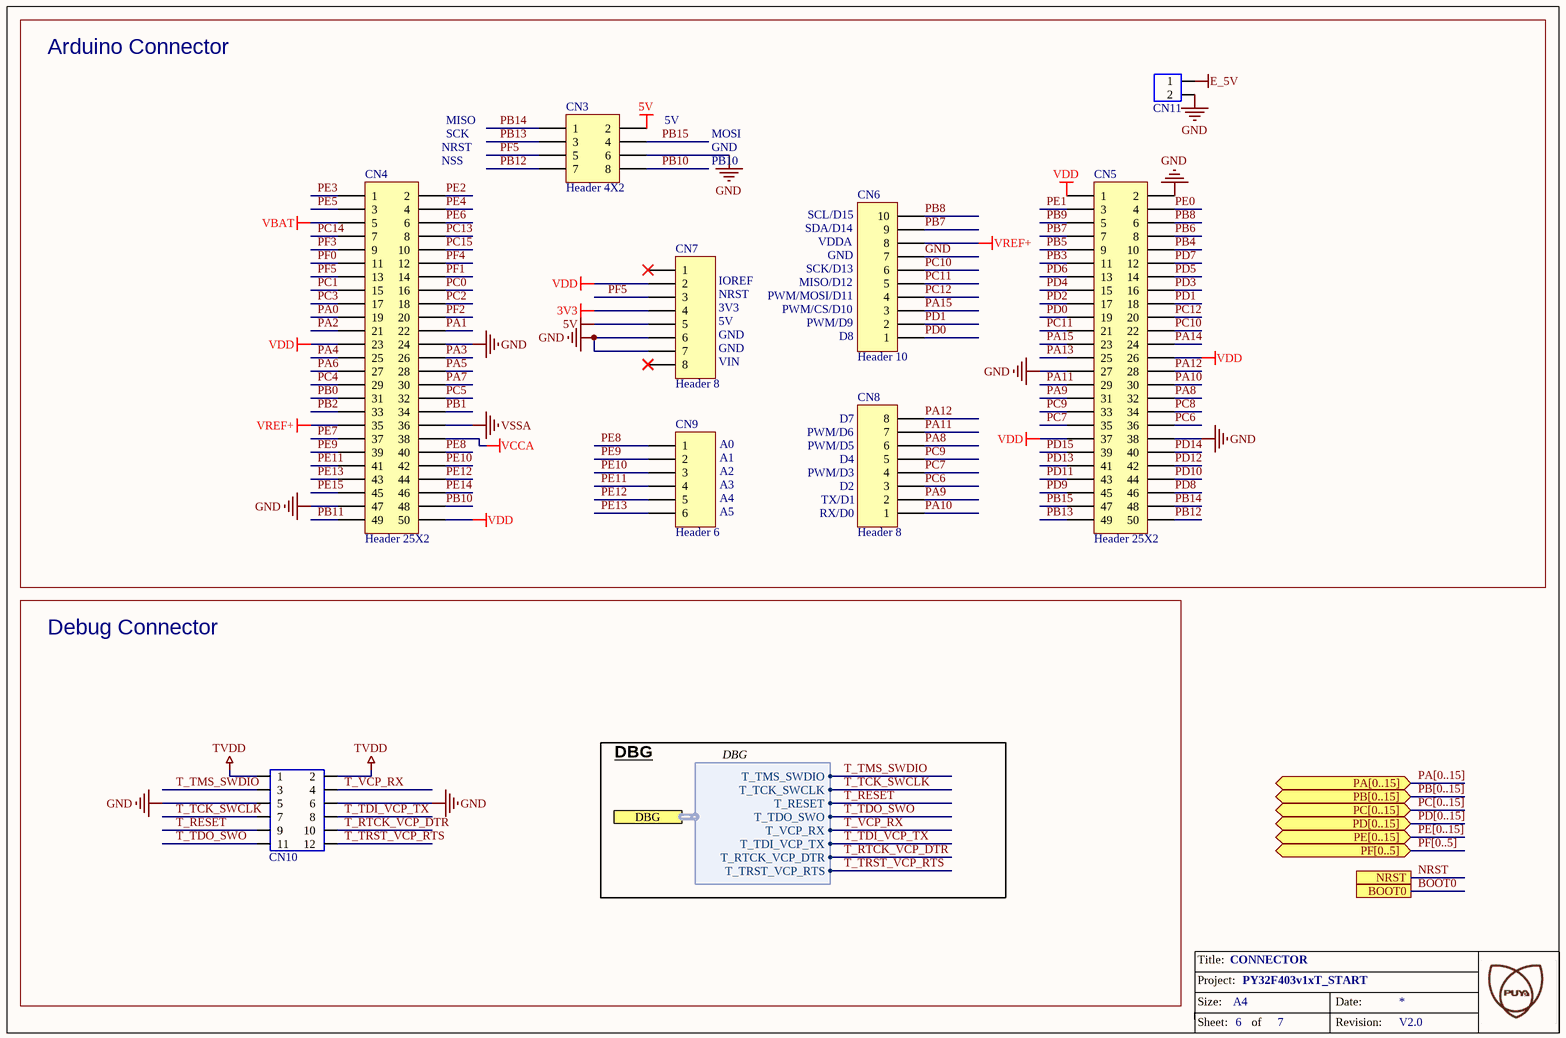
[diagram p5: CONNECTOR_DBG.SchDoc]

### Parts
CN3  Header 4X2  [HDR2X4]
CN4  Header 25X2  [HDR2X25]
CN5  Header 25X2  [HDR2X25]
CN6  Header 10  [1*10P_FEMALE]
CN7  Header 8  [1*8P_FEMALE]
CN8  Header 8  [1*8P_FEMALE]
CN9  Header 6  [1*6P_FEMALE]
CN10  CON6x2  [CON6x2]  (value not drawn)
CN11  CON2  [CON2]  (value not drawn)

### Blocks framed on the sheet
Arduino Connector: CN3-CN9 CN11
Debug Connector: CN10

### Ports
BOOT0, DBG (harness DBG), NRST, PA[0..15] (bidir), PB[0..15] (bidir), PC[0..15] (bidir), PD[0..15] (bidir), PE[0..15] (bidir), PF[0..5] (bidir)

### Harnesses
DBG: T_VCP_RX, T_TDO_SWO, T_RESET, T_TMS_SWDIO, T_TDI_VCP_TX, T_TCK_SWCLK, T_RTCK_VCP_DTR, T_TRST_VCP_RTS

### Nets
3V3: CN7.4
5V: CN3.2 CN7.5
E_5V: CN11.1
GND: CN3.6 CN4.24 CN4.47 CN5.2 CN5.27 CN5.38 CN6.7 CN7.6 CN7.7 CN10.5 CN10.6 CN11.2
TVDD: CN10.1 CN10.2
VBAT: CN4.5
VCCA: CN4.38
VDD: CN4.23 CN4.50 CN5.1 CN5.26 CN5.37 CN7.2
VREF+: CN4.35 CN6.8
VSSA: CN4.36
BOOT0: CN5.6 CN6.10 ; port BOOT0  [also labelled PB8]
PA0: CN4.19
PA1: CN4.22
PA2: CN4.21
PA3: CN4.26
PA4: CN4.25
PA5: CN4.28
PA6: CN4.27
PA7: CN4.30
PA8: CN5.32 CN8.6
PA9: CN5.31 CN8.2
PA10: CN5.30 CN8.1
PA11: CN5.29 CN8.7
PA12: CN5.28 CN8.8
PA13: CN5.25
PA14: CN5.24
PA15: CN5.23 CN6.3
PB0: CN4.31
PB1: CN4.34
PB2: CN4.33
PB3: CN5.11
PB4: CN5.10
PB5: CN5.9
PB6: CN5.8
PB7: CN5.7 CN6.9
PB9: CN5.5
PB10: CN3.8 CN4.48
PB11: CN4.49
PB12: CN3.7 CN5.50
PB13: CN3.3 CN5.49
PB14: CN3.1 CN5.48
PB15: CN3.4 CN5.47
PC0: CN4.16
PC1: CN4.15
PC2: CN4.18
PC3: CN4.17
PC4: CN4.29
PC5: CN4.32
PC6: CN5.36 CN8.3
PC7: CN5.35 CN8.4
PC8: CN5.34
PC9: CN5.33 CN8.5
PC10: CN5.22 CN6.6
PC11: CN5.21 CN6.5
PC12: CN5.20 CN6.4
PC13: CN4.8
PC14: CN4.7
PC15: CN4.10
PD0: CN5.19 CN6.1
PD1: CN5.18 CN6.2
PD2: CN5.17
PD3: CN5.16
PD4: CN5.15
PD5: CN5.14
PD6: CN5.13
PD7: CN5.12
PD8: CN5.46
PD9: CN5.45
PD10: CN5.44
PD11: CN5.43
PD12: CN5.42
PD13: CN5.41
PD14: CN5.40
PD15: CN5.39
PE0: CN5.4
PE1: CN5.3
PE2: CN4.2
PE3: CN4.1
PE4: CN4.4
PE5: CN4.3
PE6: CN4.6
PE7: CN4.37
PE8: CN4.40 CN9.1
PE9: CN4.39 CN9.2
PE10: CN4.42 CN9.3
PE11: CN4.41 CN9.4
PE12: CN4.44 CN9.5
PE13: CN4.43 CN9.6
PE14: CN4.46
PE15: CN4.45
PF0: CN4.11
PF1: CN4.14
PF2: CN4.20
PF3: CN4.9
PF4: CN4.12
PF5: CN3.5 CN4.13 CN7.3
T_RESET: CN10.9 ; port DBG.T_RESET
T_RTCK_VCP_DTR: CN10.10 ; port DBG.T_RTCK_VCP_DTR
T_TCK_SWCLK: CN10.7 ; port DBG.T_TCK_SWCLK
T_TDI_VCP_TX: CN10.8 ; port DBG.T_TDI_VCP_TX
T_TDO_SWO: CN10.11 ; port DBG.T_TDO_SWO
T_TMS_SWDIO: CN10.3 ; port DBG.T_TMS_SWDIO
T_TRST_VCP_RTS: CN10.12 ; port DBG.T_TRST_VCP_RTS
T_VCP_RX: CN10.4 ; port DBG.T_VCP_RX

Not connected (* = marked no-connect by the designer): CN7 1* 8*

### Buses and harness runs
bus PA[0..15] = port PA[0..15]
bus PB[0..15] = port PB[0..15]
bus PC[0..15] = port PC[0..15]
bus PD[0..15] = port PD[0..15]
bus PE[0..15] = port PE[0..15]
bus PF[0..5] = port PF[0..5]

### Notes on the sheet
- (near CN4) NRST
- (near CN4) NSS
- MISO
- SCK
- (near CN3) 5V
- MOSI
- GND
- PB10
- (near CN6) SDA/D14
- (near CN6) SCL/D15
- VDDA
- (near CN7) IOREF
- (near CN7) NRST
- (near CN7) 3V3
- PWM/MOSI/D11
- PWM/CS/D10
- (near CN6) MISO/D12
- (near CN6) SCK/D13
- (near CN6) GND
- (near CN7) 5V
- (near CN7) GND
- (near CN7) VIN
- PWM/D9
- (near CN6) D8
- (near CN9) A0
- PWM/D6
- PWM/D5
- (near CN8) D7
- (near CN9) A1
- (near CN9) A2
- (near CN9) A3
- (near CN9) A4
- (near CN9) A5
- (near CN8) PWM/D3
- (near CN8) RX/D0
- (near CN8) TX/D1
- (near CN8) D4
- (near CN8) D2
- DBG

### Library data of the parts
CN3 = Header 4X2: Header, 4-Pin, Dual row
CN4 CN5 = Header 25X2: Header, 25-Pin, Dual row
CN6 = Header 10: Header, 10-Pin
CN7 CN8 = Header 8: Header, 8-Pin
CN9 = Header 6: Header, 6-Pin
CN10 = CON6x2: PCB DECAL: CON5x2

## Sheet POWER.SchDoc: POWER_USB
size A4; Revision: V2.0; SheetNumber: 4; SheetTotal: 7; Project: PY32F403v1xT_START
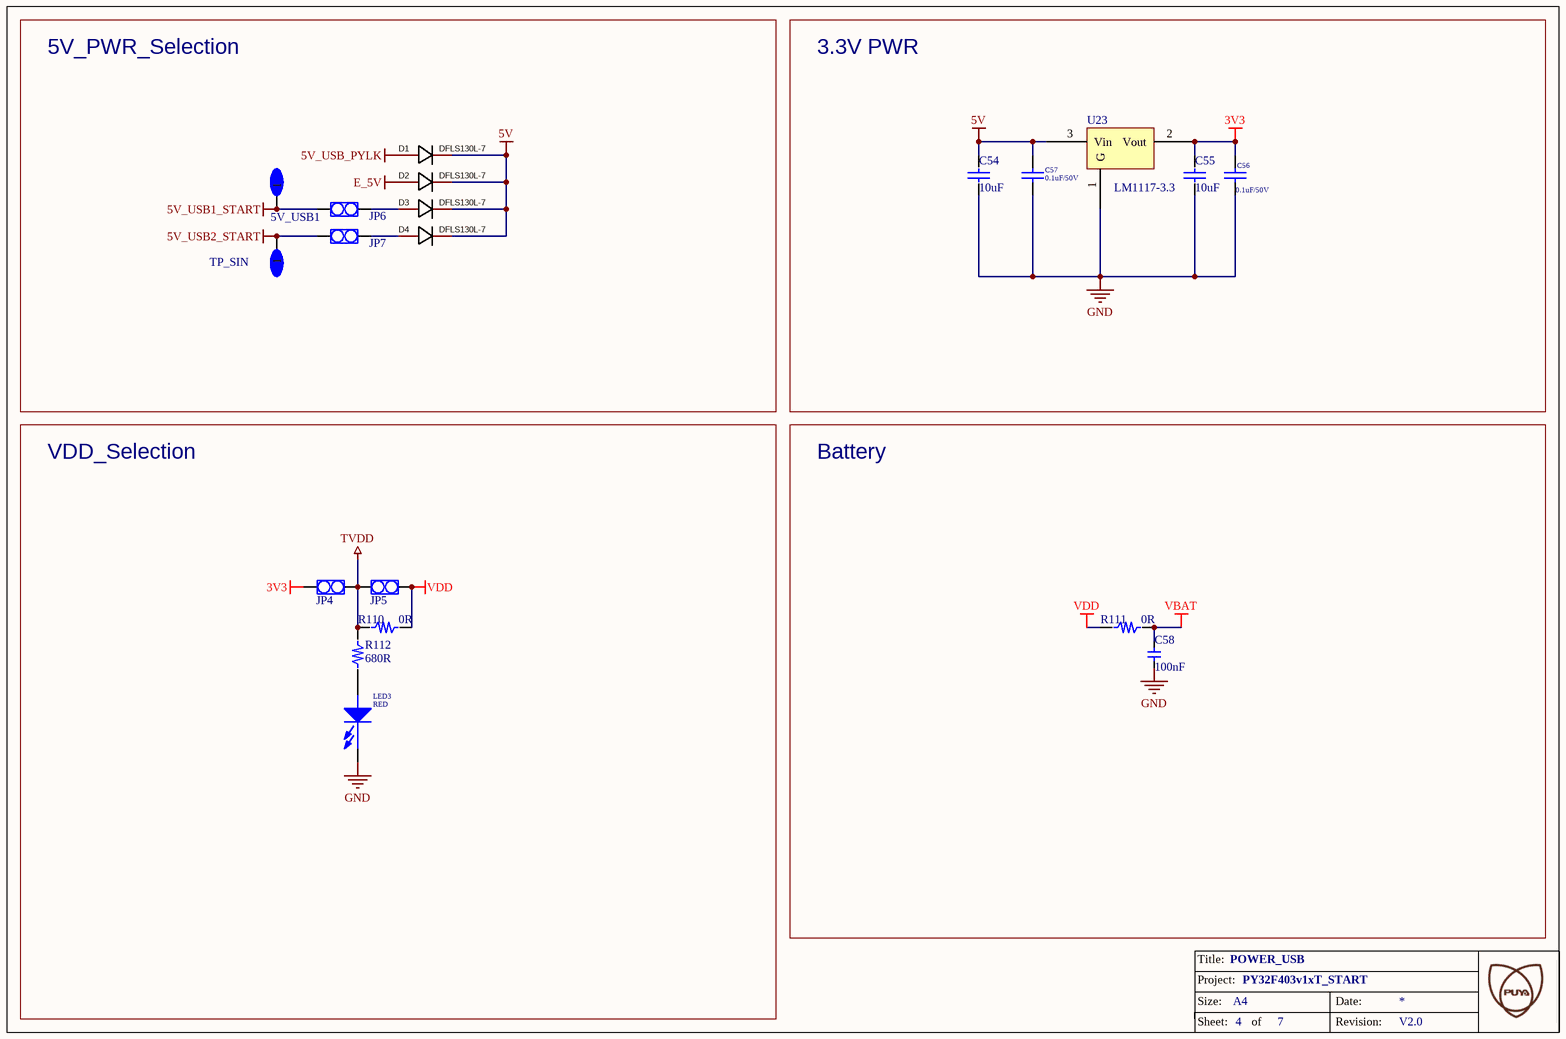
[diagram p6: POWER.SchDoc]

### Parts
5V_USB1  TP_SIN  [TP_SIN]  (value not drawn)
5V_USB2  TP_SIN  [TP_SIN]
C54  10uF  [C0805]
C55  10uF  [C0805]
C56  0.1uF/50V  [c0603cap]
C57  0.1uF/50V  [c0603cap]
C58  100nF  [C0603]
D1  DFLS130L-7  [POWERDI-123_L2.8-W1.8-LS3.7-RD]
D2  DFLS130L-7  [POWERDI-123_L2.8-W1.8-LS3.7-RD]
D3  DFLS130L-7  [POWERDI-123_L2.8-W1.8-LS3.7-RD]
D4  DFLS130L-7  [POWERDI-123_L2.8-W1.8-LS3.7-RD]
JP4  CON2  [CON2]  (value not drawn)
JP5  CON2/NC  [CON2]  (value not drawn)
JP6  CON2  [CON2]  (value not drawn)
JP7  CON2  [CON2]  (value not drawn)
LED3  RED  [0603_LED]
R110  0R  [R0603]
R111  0R  [R0603]
R112  680R  [R0603]
U23  LM1117-3.3  [LM1117-3.3]

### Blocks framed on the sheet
5V_PWR_Selection: 5V_USB1 5V_USB2 D1-D4 JP6 JP7
3.3V PWR: C54-C57 U23
VDD_Selection: JP4 JP5 LED3 R110 R112
Battery: C58 R111

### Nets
3V3: C55.2 C56.2 JP4.1 U23.2(Vout)
5V: C54.2 C57.2 D1.1 D2.1 D3.1 D4.1 U23.3(Vin)
5V_USB1_START: 5V_USB1.1 JP6.1
5V_USB2_START: 5V_USB2.1 JP7.1
5V_USB_PYLK: D1.2
E_5V: D2.2
GND: C54.1 C55.1 C56.1 C57.1 C58.1 LED3.2(CATHODE) U23.1(G)
TVDD: JP4.2 JP5.1 R110.1 R112.2
VBAT: C58.2 R111.2
VDD: JP5.2 R110.2 R111.1
NetD3_2: D3.2 JP6.2
NetD4_2: D4.2 JP7.2
NetLED3_1: LED3.1(ANODE) R112.1

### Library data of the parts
C54 C55 = C0805: PCB DECAL: 0805
C56 = Cap: Capacitor
C57 = CAP: Capacitor; Value: 2.2uF
C58 = C0603: PCB DECAL: 0603
D1-D4 = DFLS130L-7: Manufacturer: DIODES(美台); Add into BOM: yes; Forward Voltage (Vf@If): 310mV@1A; Reverse Voltage (Vr): 30V; Average Rectified Current (Io): 1A
JP4-JP7 = CON2_DIP
LED3 = PDI-E803_Dup1
R110-R112 = R0603: PCB DECAL: 0603

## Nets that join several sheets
3V3: CONNECTOR_DBG (CN7.4), POWER (C55.2 C56.2 JP4.1 U23.2)
5V: PERIPHERA (5 pins), CONNECTOR_DBG (CN3.2 CN7.5), POWER (7 pins)
5V_USB1_START: PERIPHERA (C60.2 R89.2 U24.1 USB1.1), POWER (5V_USB1.1 JP6.1)
5V_USB2_START: PERIPHERA (C62.2 R96.2 U25.1 USB2.1), POWER (5V_USB2.1 JP7.1)
5V_USB_PYLK: PYLink (C15.2 JP1.3 U16.1), POWER (D1.2)
E_5V: CONNECTOR_DBG (CN11.1), POWER (D2.2)
GND: PYLink (63 pins), MCU (21 pins), ETH (24 pins), PERIPHERA (24 pins), CONNECTOR_DBG (12 pins), POWER (7 pins)
TVDD: PYLink (18 pins), CONNECTOR_DBG (CN10.1 CN10.2), POWER (JP4.2 JP5.1 R110.1 R112.2)
VBAT: MCU (U18.6), CONNECTOR_DBG (CN4.5), POWER (C58.2 R111.2)
VCCA: MCU (5 pins), CONNECTOR_DBG (CN4.38)
VDD: MCU (16 pins), ETH (R97.1), PERIPHERA (7 pins), CONNECTOR_DBG (6 pins), POWER (JP5.2 R110.2 R111.1)
VDD_FLASH: MCU (R48.2 R49.2), PERIPHERA (R88.2 R90.2 U21.8)
VREF+: MCU (5 pins), CONNECTOR_DBG (CN4.35 CN6.8)
VSSA: MCU (6 pins), CONNECTOR_DBG (CN4.36)
BOOT0: MCU (R65.2 U18.95), CONNECTOR_DBG (CN5.6 CN6.10)
ESMC_CLK: MCU (R44.1 R51.1), PERIPHERA (U21.6)
ESMC_CS: MCU (R43.1 R50.1), PERIPHERA (R90.1 U21.1)
ESMC_IO0: MCU (R47.1 R52.1), PERIPHERA (U21.5)
ESMC_IO1: MCU (R46.1 R53.1), PERIPHERA (U21.2)
ESMC_IO2: MCU (R48.1 R55.1), PERIPHERA (U21.3)
ESMC_IO3: MCU (R49.1 R56.1), PERIPHERA (U21.7)
LAN8720_CRS_DV: MCU (R58.1), ETH (U22.11)
LAN8720_MCO: MCU (R69.1), ETH (R108.2)
LAN8720_MDC: MCU (R61.1), ETH (U22.13)
LAN8720_MDIO: MCU (R66.1), ETH (U22.12)
LAN8720_nINT: MCU (R67.1), ETH (U22.14)
LAN8720_nRST: MCU (R68.1), ETH (U22.15)
LAN8720_RXD0: MCU (R59.1), ETH (U22.8)
LAN8720_RXD1: MCU (R60.1), ETH (U22.7)
LAN8720_TXD0: MCU (R62.1), ETH (U22.17)
LAN8720_TXD1: MCU (R63.1), ETH (U22.18)
LAN8720_TXEN: MCU (R64.1), ETH (U22.16)
PA0: MCU (U18.20), CONNECTOR_DBG (CN4.19)
PA1: MCU (R67.2 U18.21), CONNECTOR_DBG (CN4.22)
PA2: MCU (R66.2 U18.22), CONNECTOR_DBG (CN4.21)
PA3: MCU (R51.2 U18.25), CONNECTOR_DBG (CN4.26)
PA4: MCU (R43.2 U18.26), CONNECTOR_DBG (CN4.25)
PA5: MCU (U18.27), PERIPHERA (R114.2), CONNECTOR_DBG (CN4.28)
PA6: MCU (R46.2 R56.2 U18.28), CONNECTOR_DBG (CN4.27)
PA7: MCU (R47.2 R55.2 U18.29), CONNECTOR_DBG (CN4.30)
PA8: MCU (R69.2 U18.69), CONNECTOR_DBG (CN5.32 CN8.6)
PA9: MCU (JP3.3 U18.70), CONNECTOR_DBG (CN5.31 CN8.2)
PA10: MCU (JP3.4 U18.71), CONNECTOR_DBG (CN5.30 CN8.1)
PA11: MCU (U18.72), PERIPHERA (R87.1), CONNECTOR_DBG (CN5.29 CN8.7)
PA12: MCU (U18.73), PERIPHERA (R86.1), CONNECTOR_DBG (CN5.28 CN8.8)
PA13: MCU (R70.2 U18.76), CONNECTOR_DBG (CN5.25)
PA14: MCU (R71.2 U18.77), CONNECTOR_DBG (CN5.24)
PA15: MCU (R75.2 U18.78), CONNECTOR_DBG (CN5.23 CN6.3)
PB0: MCU (R53.2 U18.32), CONNECTOR_DBG (CN4.31)
PB1: MCU (R52.2 U18.33), CONNECTOR_DBG (CN4.34)
PB2: MCU (U18.34), CONNECTOR_DBG (CN4.33)
PB3: MCU (R44.2 R73.2 U18.90), CONNECTOR_DBG (CN5.11)
PB4: MCU (R76.2 U18.91), CONNECTOR_DBG (CN5.10)
PB5: MCU (R81.2 U18.92), CONNECTOR_DBG (CN5.9)
PB6: MCU (R79.2 U18.93), CONNECTOR_DBG (CN5.8)
PB7: MCU (U18.94), PERIPHERA (R83.1), CONNECTOR_DBG (CN5.7 CN6.9)
PB9: MCU (U18.96), CONNECTOR_DBG (CN5.5)
PB10: MCU (U18.47), CONNECTOR_DBG (CN3.8 CN4.48)
PB11: MCU (R64.2 U18.50), CONNECTOR_DBG (CN4.49)
PB12: MCU (R62.2 U18.51), CONNECTOR_DBG (CN3.7 CN5.50)
PB13: MCU (R63.2 U18.52), CONNECTOR_DBG (CN3.3 CN5.49)
PB14: MCU (U18.53), CONNECTOR_DBG (CN3.1 CN5.48)
PB15: MCU (U18.54), CONNECTOR_DBG (CN3.4 CN5.47)
PC0: MCU (U18.15), PERIPHERA (R95.1), CONNECTOR_DBG (CN4.16)
PC1: MCU (R61.2 U18.16), PERIPHERA (R94.1), CONNECTOR_DBG (CN4.15)
PC2: MCU (U18.17), PERIPHERA (R92.1), CONNECTOR_DBG (CN4.18)
PC3: MCU (U18.18), PERIPHERA (R96.1), CONNECTOR_DBG (CN4.17)
PC4: MCU (R59.2 U18.30), CONNECTOR_DBG (CN4.29)
PC5: MCU (R60.2 U18.31), CONNECTOR_DBG (CN4.32)
PC6: MCU (U18.65), CONNECTOR_DBG (CN5.36 CN8.3)
PC7: MCU (U18.66), CONNECTOR_DBG (CN5.35 CN8.4)
PC8: MCU (R68.2 U18.67), CONNECTOR_DBG (CN5.34)
PC9: MCU (U18.68), CONNECTOR_DBG (CN5.33 CN8.5)
PC10: MCU (R80.2 U18.79), CONNECTOR_DBG (CN5.22 CN6.6)
PC11: MCU (U18.80), CONNECTOR_DBG (CN5.21 CN6.5)
PC12: MCU (U18.81), CONNECTOR_DBG (CN5.20 CN6.4)
PC13: MCU (U18.7), CONNECTOR_DBG (CN4.8)
PC14: MCU (R37.1), CONNECTOR_DBG (CN4.7)
PC15: MCU (R38.1), CONNECTOR_DBG (CN4.10)
PD0: MCU (U18.82), CONNECTOR_DBG (CN5.19 CN6.1)
PD1: MCU (U18.83), CONNECTOR_DBG (CN5.18 CN6.2)
PD2: MCU (R50.2 U18.84), CONNECTOR_DBG (CN5.17)
PD3: MCU (U18.85), CONNECTOR_DBG (CN5.16)
PD4: MCU (U18.86), CONNECTOR_DBG (CN5.15)
PD5: MCU (U18.87), CONNECTOR_DBG (CN5.14)
PD6: MCU (U18.88), CONNECTOR_DBG (CN5.13)
PD7: MCU (U18.89), CONNECTOR_DBG (CN5.12)
PD8: MCU (R58.2 U18.55), CONNECTOR_DBG (CN5.46)
PD9: MCU (U18.56), PERIPHERA (R91.1), CONNECTOR_DBG (CN5.45)
PD10: MCU (U18.57), PERIPHERA (R117.2), CONNECTOR_DBG (CN5.44)
PD11: MCU (U18.58), CONNECTOR_DBG (CN5.43)
PD12: MCU (U18.59), CONNECTOR_DBG (CN5.42)
PD13: MCU (U18.60), CONNECTOR_DBG (CN5.41)
PD14: MCU (U18.61), CONNECTOR_DBG (CN5.40)
PD15: MCU (U18.62), CONNECTOR_DBG (CN5.39)
PE0: MCU (U18.97), CONNECTOR_DBG (CN5.4)
PE1: MCU (U18.98), CONNECTOR_DBG (CN5.3)
PE2: MCU (U18.1), CONNECTOR_DBG (CN4.2)
PE3: MCU (U18.2), CONNECTOR_DBG (CN4.1)
PE4: MCU (U18.3), CONNECTOR_DBG (CN4.4)
PE5: MCU (U18.4), CONNECTOR_DBG (CN4.3)
PE6: MCU (U18.5), CONNECTOR_DBG (CN4.6)
PE7: MCU (U18.38), CONNECTOR_DBG (CN4.37)
PE8: MCU (U18.39), CONNECTOR_DBG (CN4.40 CN9.1)
PE9: MCU (U18.40), CONNECTOR_DBG (CN4.39 CN9.2)
PE10: MCU (U18.41), CONNECTOR_DBG (CN4.42 CN9.3)
PE11: MCU (U18.42), CONNECTOR_DBG (CN4.41 CN9.4)
PE12: MCU (U18.43), CONNECTOR_DBG (CN4.44 CN9.5)
PE13: MCU (U18.44), CONNECTOR_DBG (CN4.43 CN9.6)
PE14: MCU (U18.45), CONNECTOR_DBG (CN4.46)
PE15: MCU (U18.46), CONNECTOR_DBG (CN4.45)
PF0: MCU (R40.1), CONNECTOR_DBG (CN4.11)
PF1: MCU (R41.1), CONNECTOR_DBG (CN4.14)
PF2: MCU (U18.19), CONNECTOR_DBG (CN4.20)
PF3: MCU (U18.10), CONNECTOR_DBG (CN4.9)
PF4: MCU (U18.11), CONNECTOR_DBG (CN4.12)
PF5: MCU (R54.2 U18.14), CONNECTOR_DBG (CN3.5 CN4.13 CN7.3)
T_RESET: PYLink (CN1.9 R17.2 U4.4), MCU (R72.1), CONNECTOR_DBG (CN10.9)
T_RTCK_VCP_DTR: PYLink (CN1.10 R9.2 U3.5), CONNECTOR_DBG (CN10.10)
T_TCK_SWCLK: PYLink (CN1.7 R6.2 U4.5), MCU (R71.1), CONNECTOR_DBG (CN10.7)
T_TDI_VCP_TX: PYLink (CN1.8 R21.2 U3.4), MCU (JP3.6 R75.1), CONNECTOR_DBG (CN10.8)
T_TDO_SWO: PYLink (CN1.11 R12.2 U4.3), MCU (R73.1), CONNECTOR_DBG (CN10.11)
T_TMS_SWDIO: PYLink (CN1.3 R2.2 U4.1), CONNECTOR_DBG (CN10.3)
T_TRST_VCP_RTS: PYLink (CN1.12 R13.2 U3.1), MCU (R76.1), CONNECTOR_DBG (CN10.12)
T_VCP_RX: PYLink (CN1.4 R22.1 R24.2 U3.3), MCU (JP3.5), CONNECTOR_DBG (CN10.4)
USB1_ID: MCU (JP3.2), PERIPHERA (R84.1)
USB1_VBUS: MCU (JP3.1), PERIPHERA (R89.1)
USER_KEY: MCU (R79.1), PERIPHERA (C39.2 K3.1 R82.2 U20.1)
USER_LED: MCU (R80.1 R81.1), PERIPHERA (LED2.2)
